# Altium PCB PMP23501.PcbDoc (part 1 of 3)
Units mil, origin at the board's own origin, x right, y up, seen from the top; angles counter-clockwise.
Board outline 4950 x 3450 mil, 4 copper layers (Top Layer, Layer 1, Layer 2, Bottom Layer), stack 70.356 mil thick; 186 components, 84 nets, 554 pads, 643 vias.
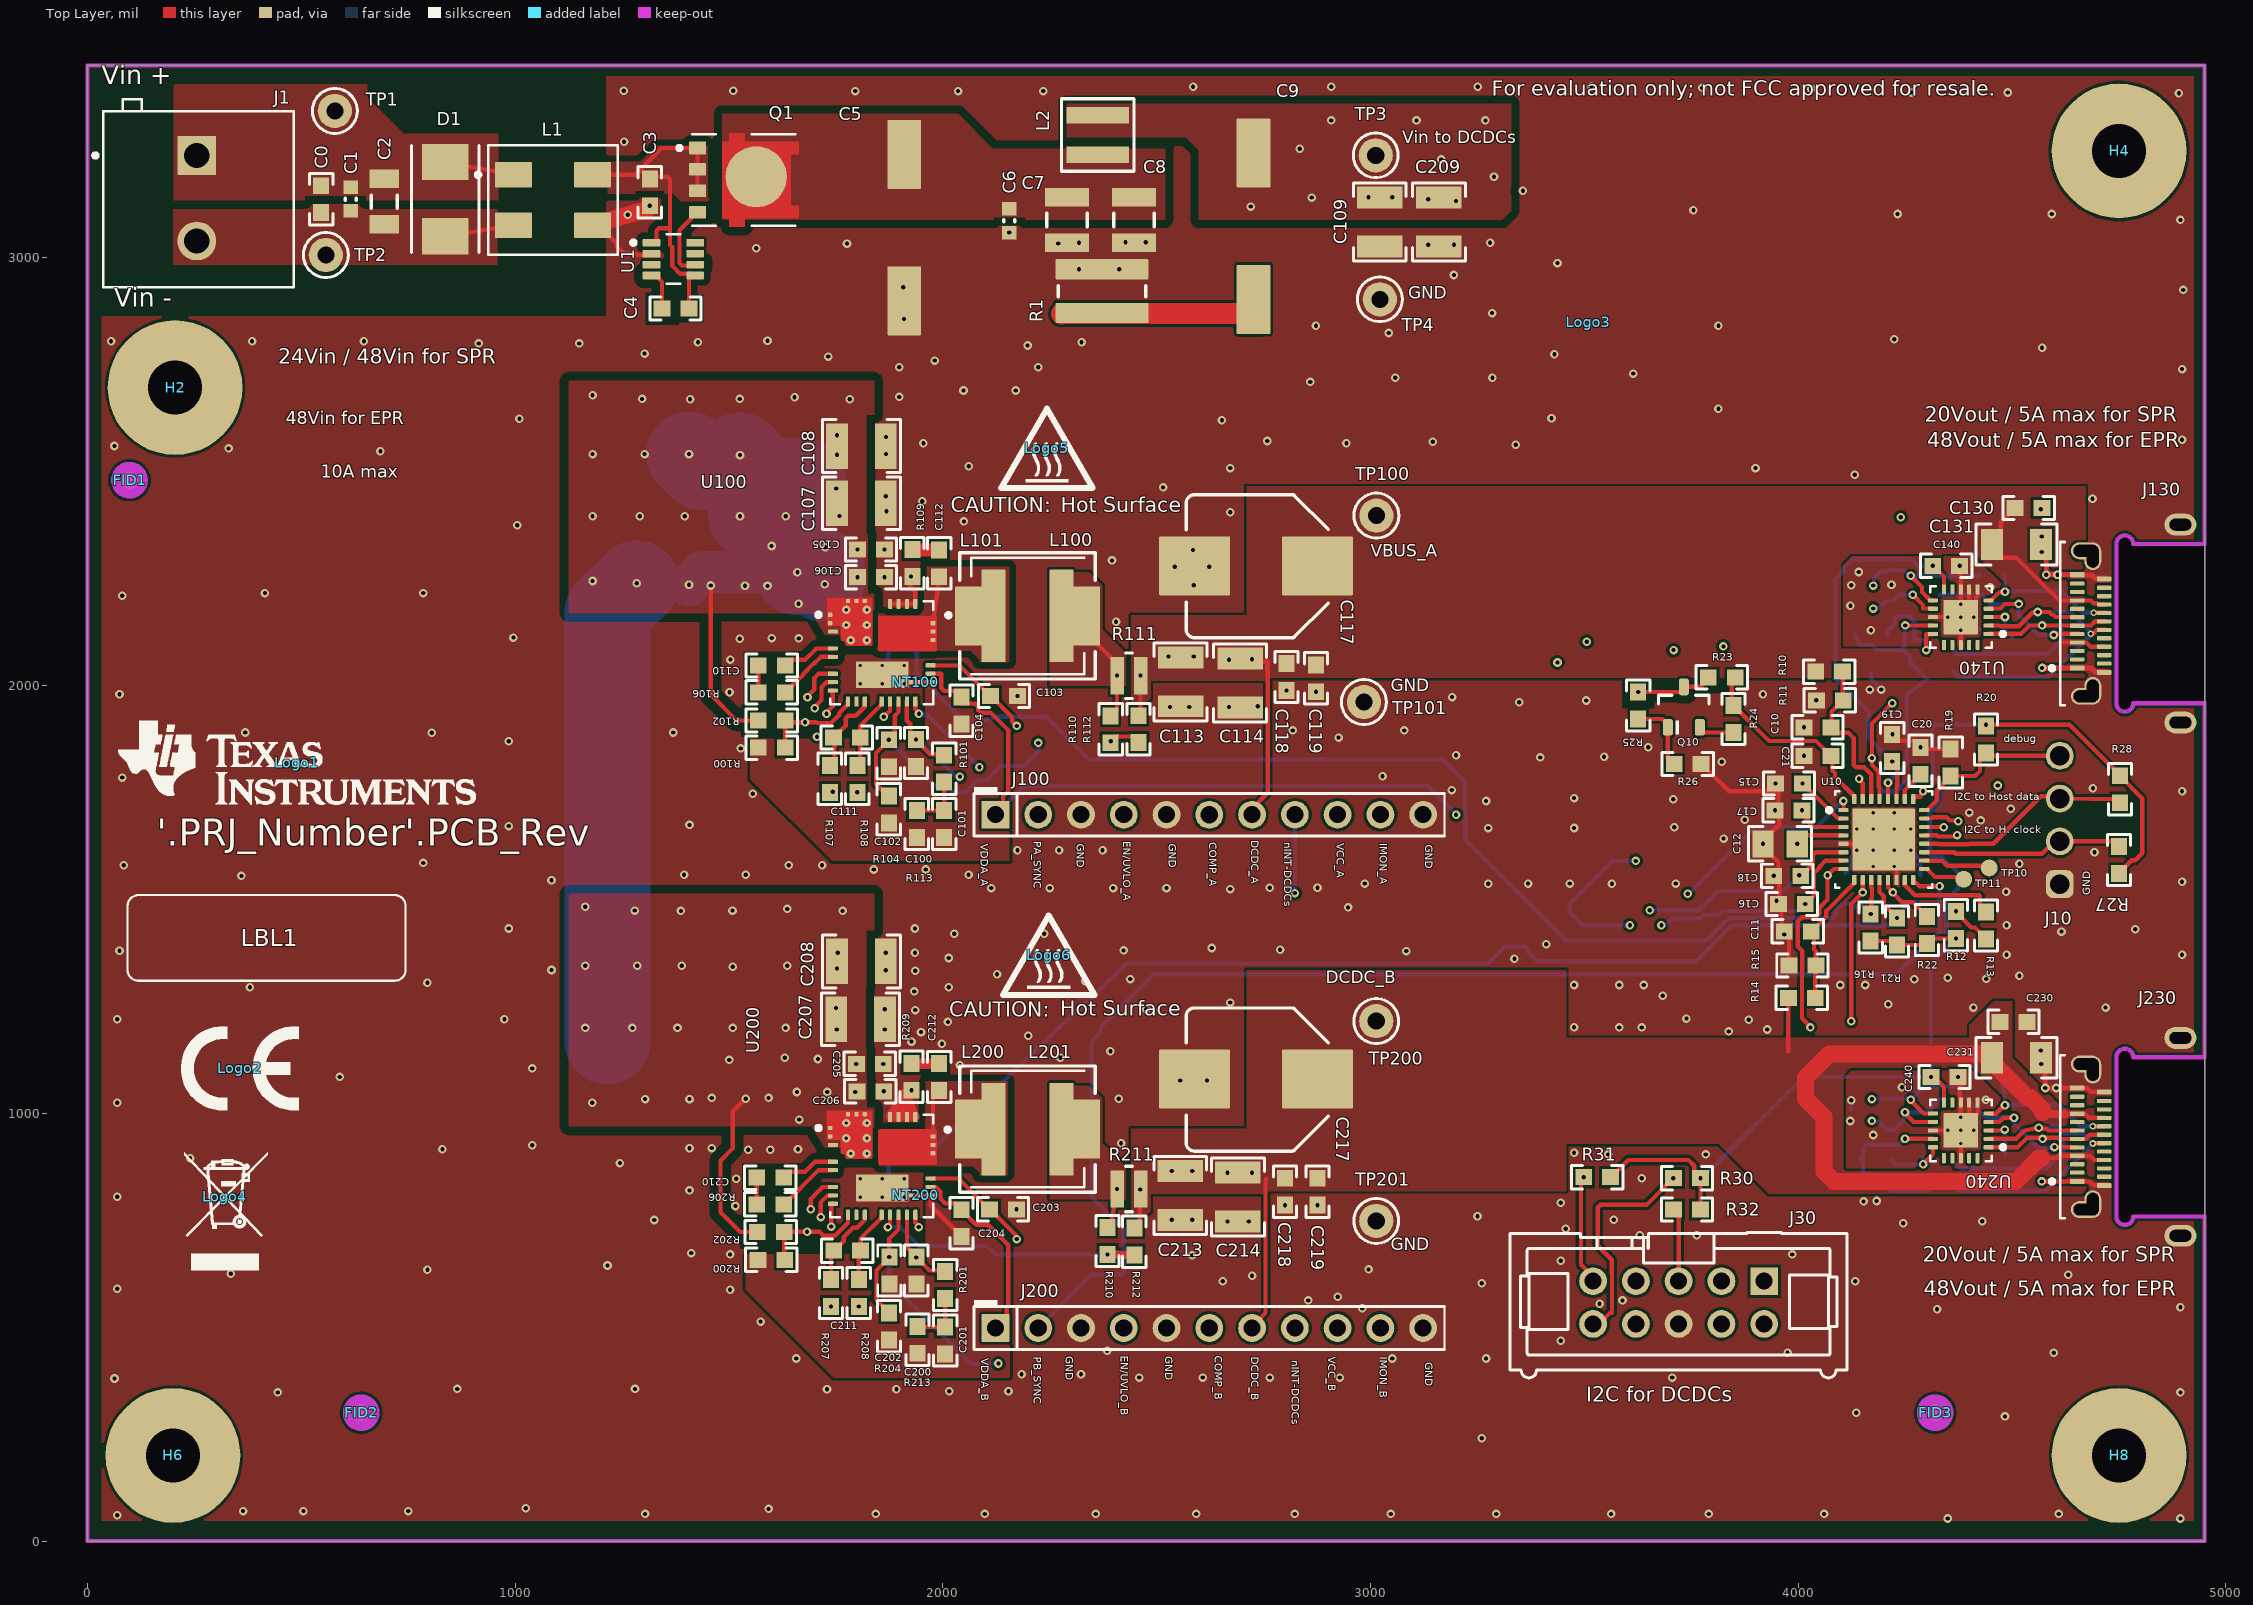
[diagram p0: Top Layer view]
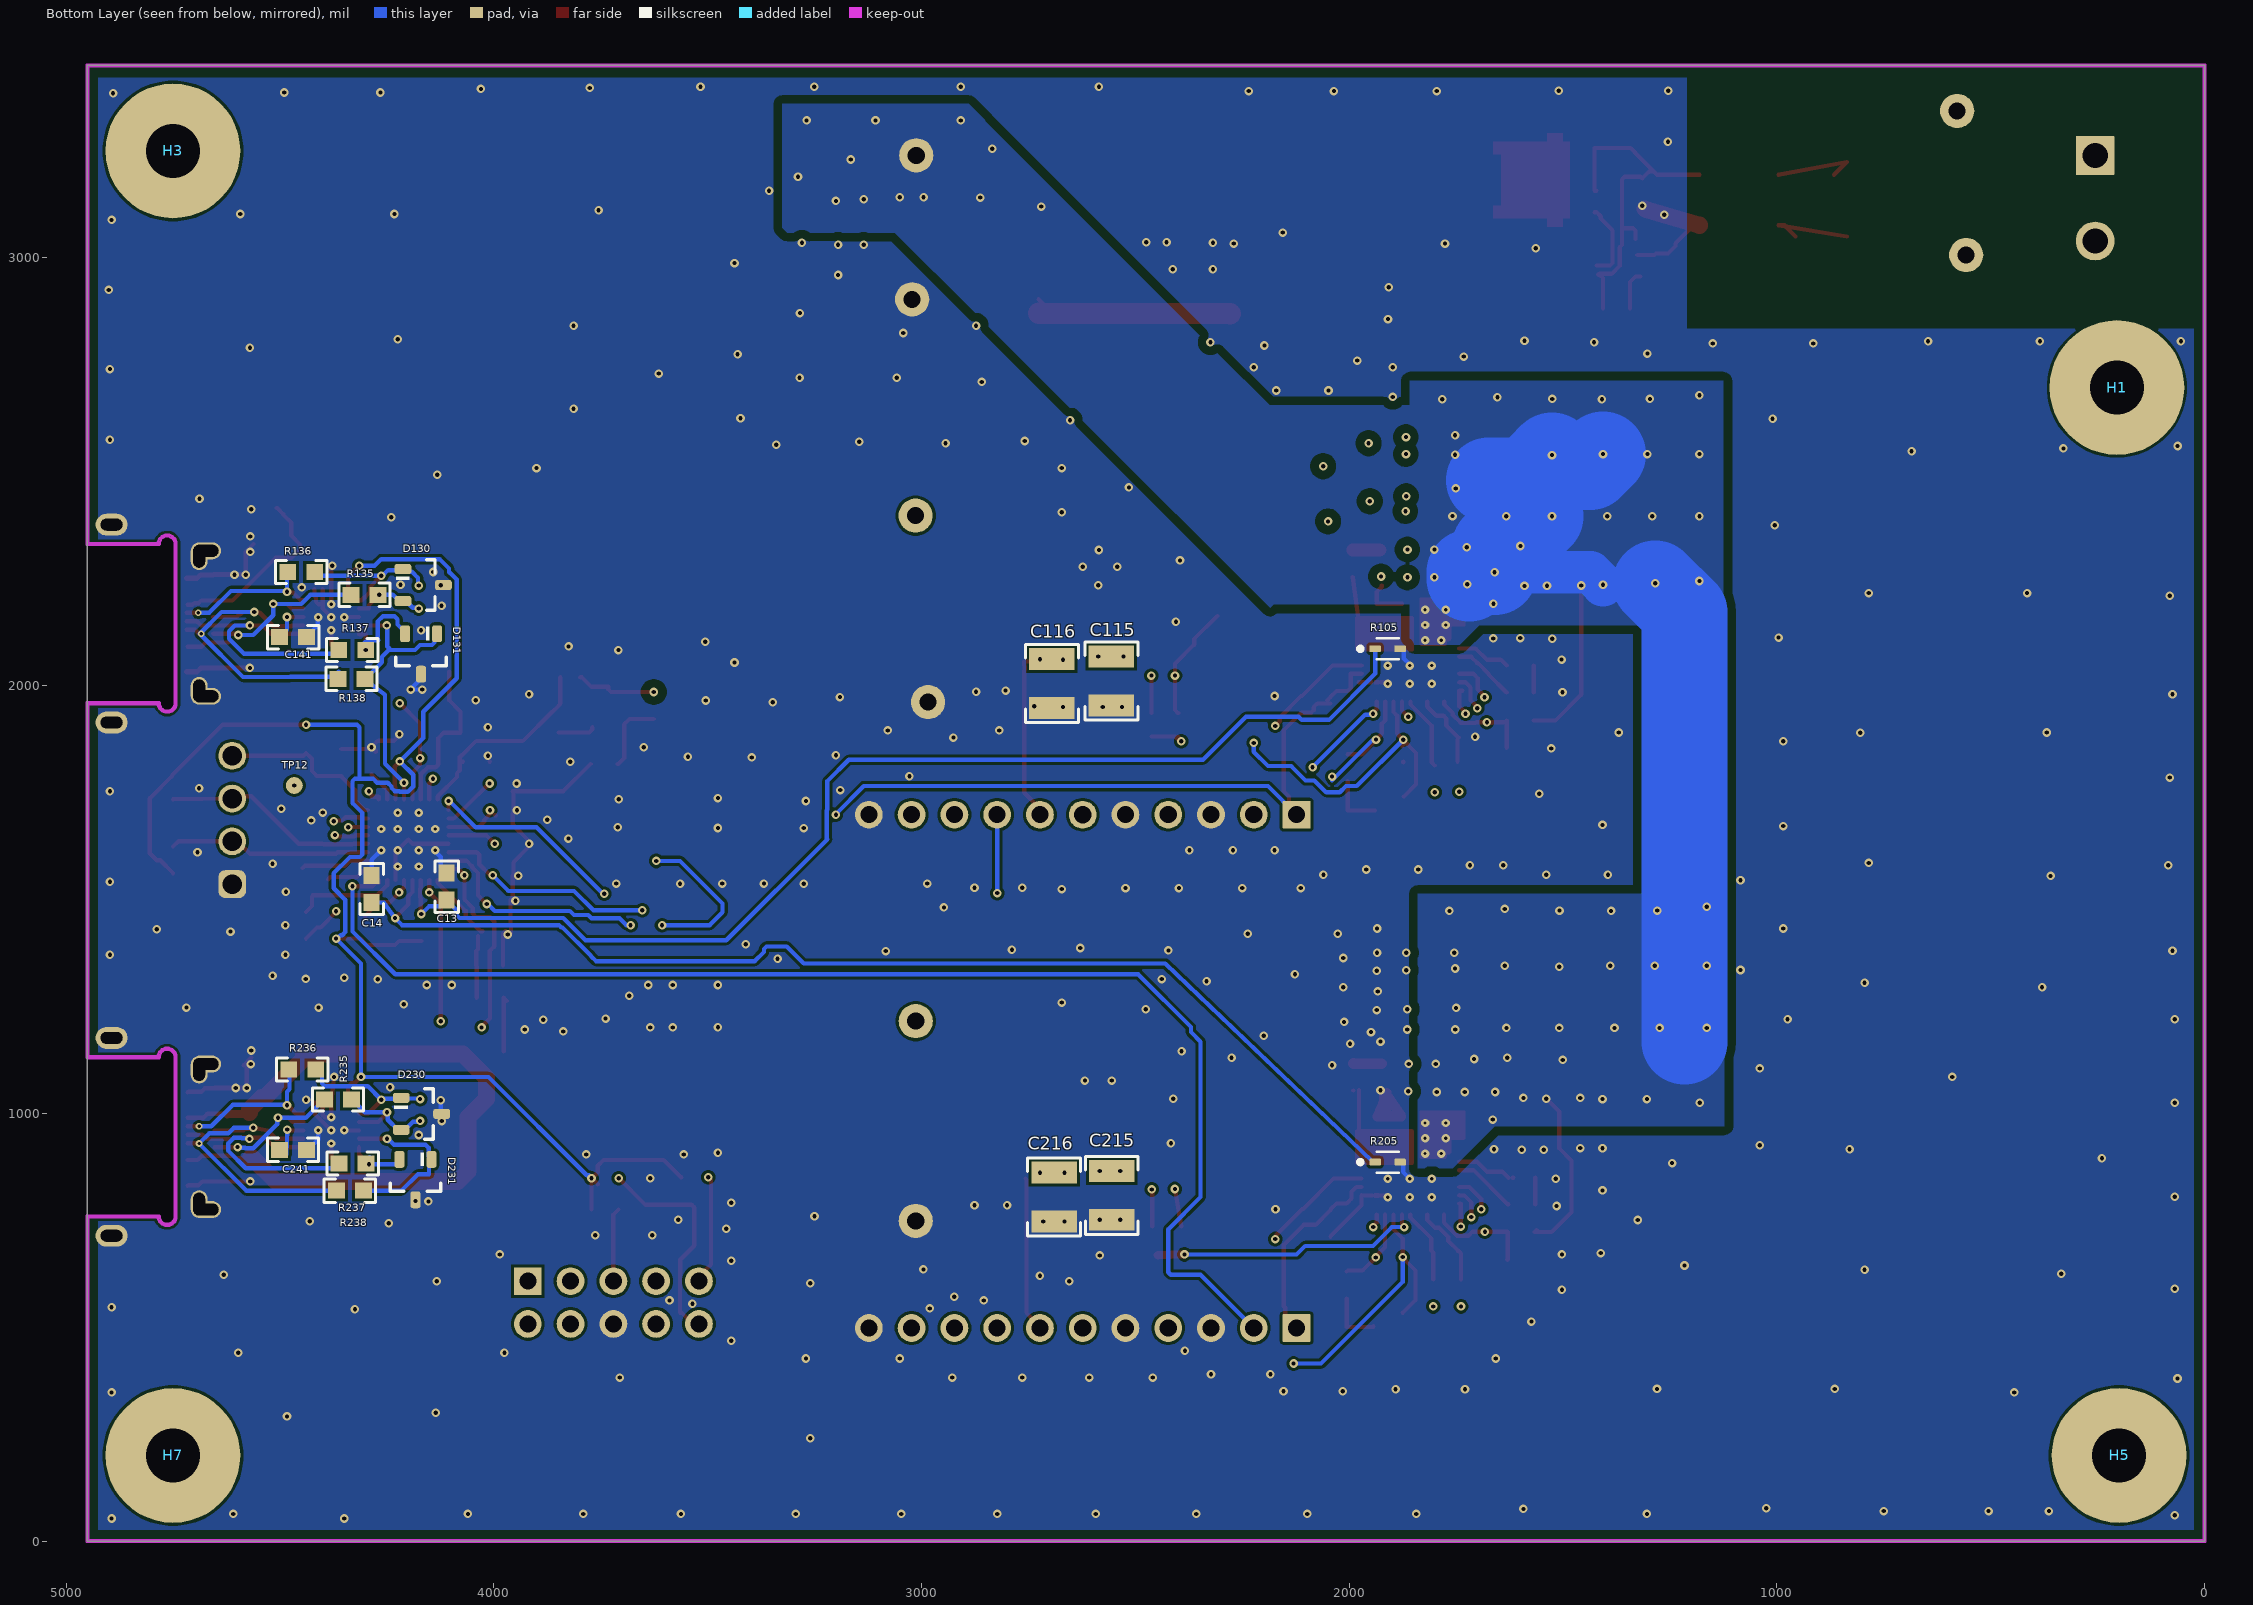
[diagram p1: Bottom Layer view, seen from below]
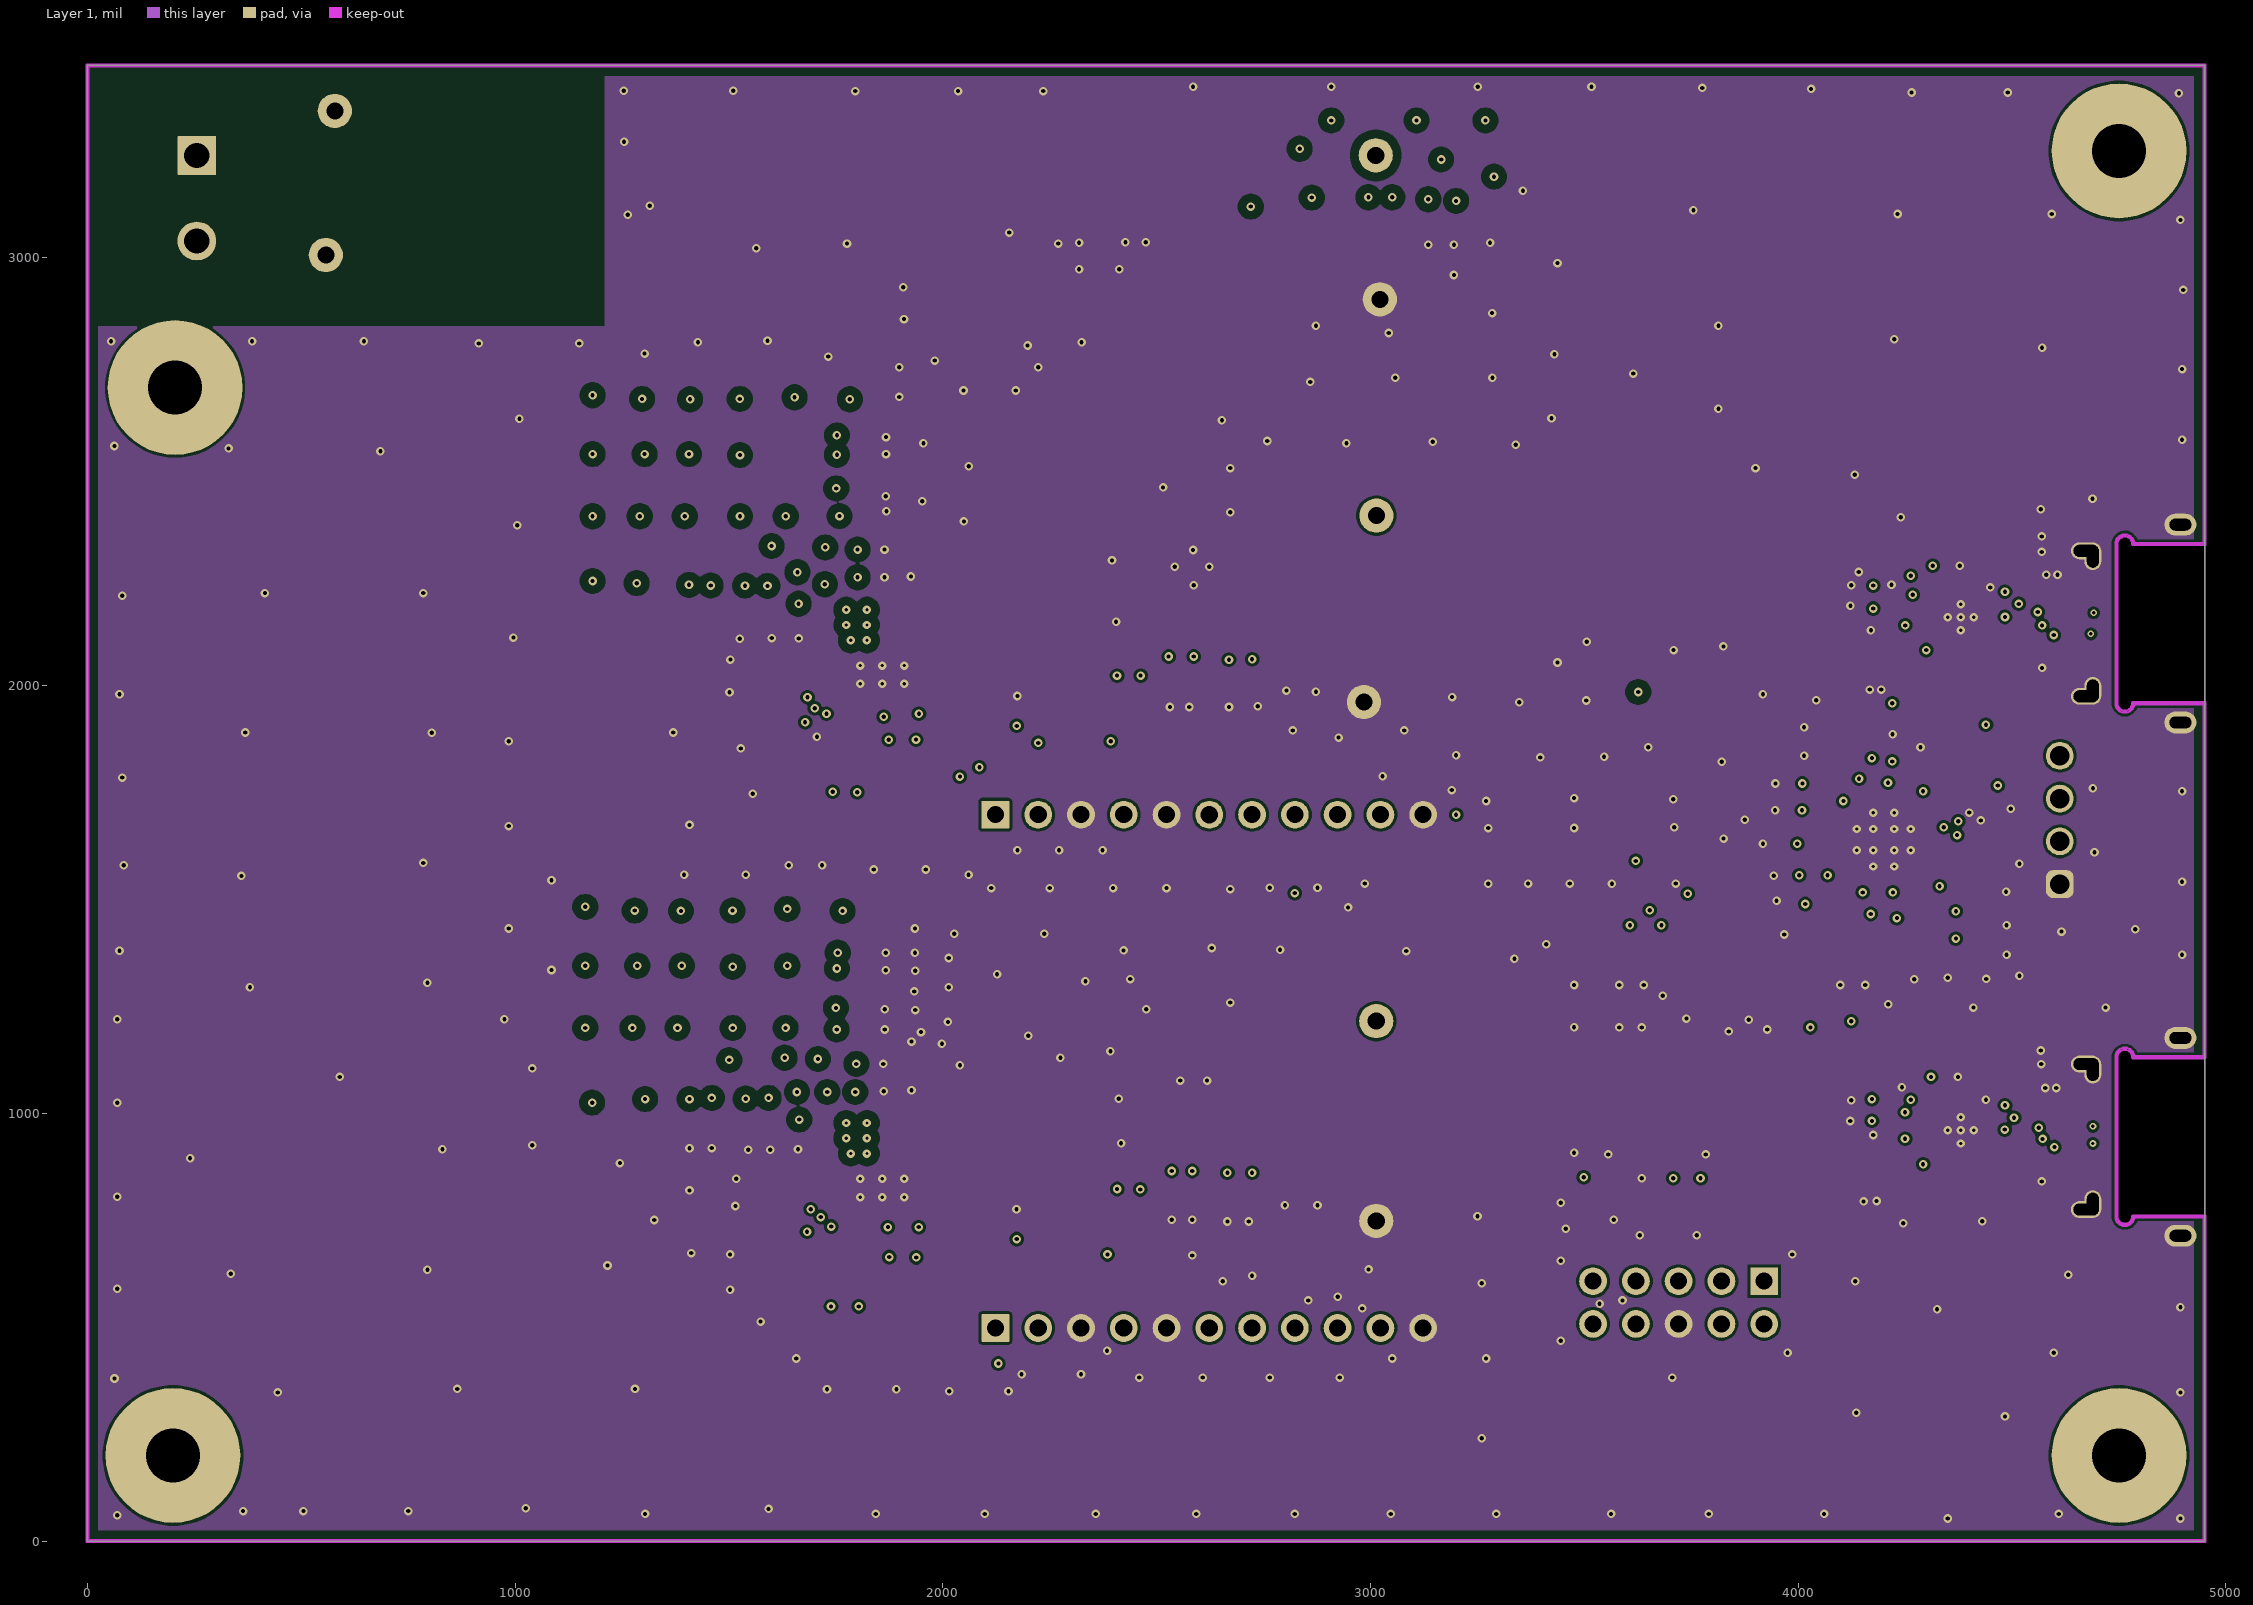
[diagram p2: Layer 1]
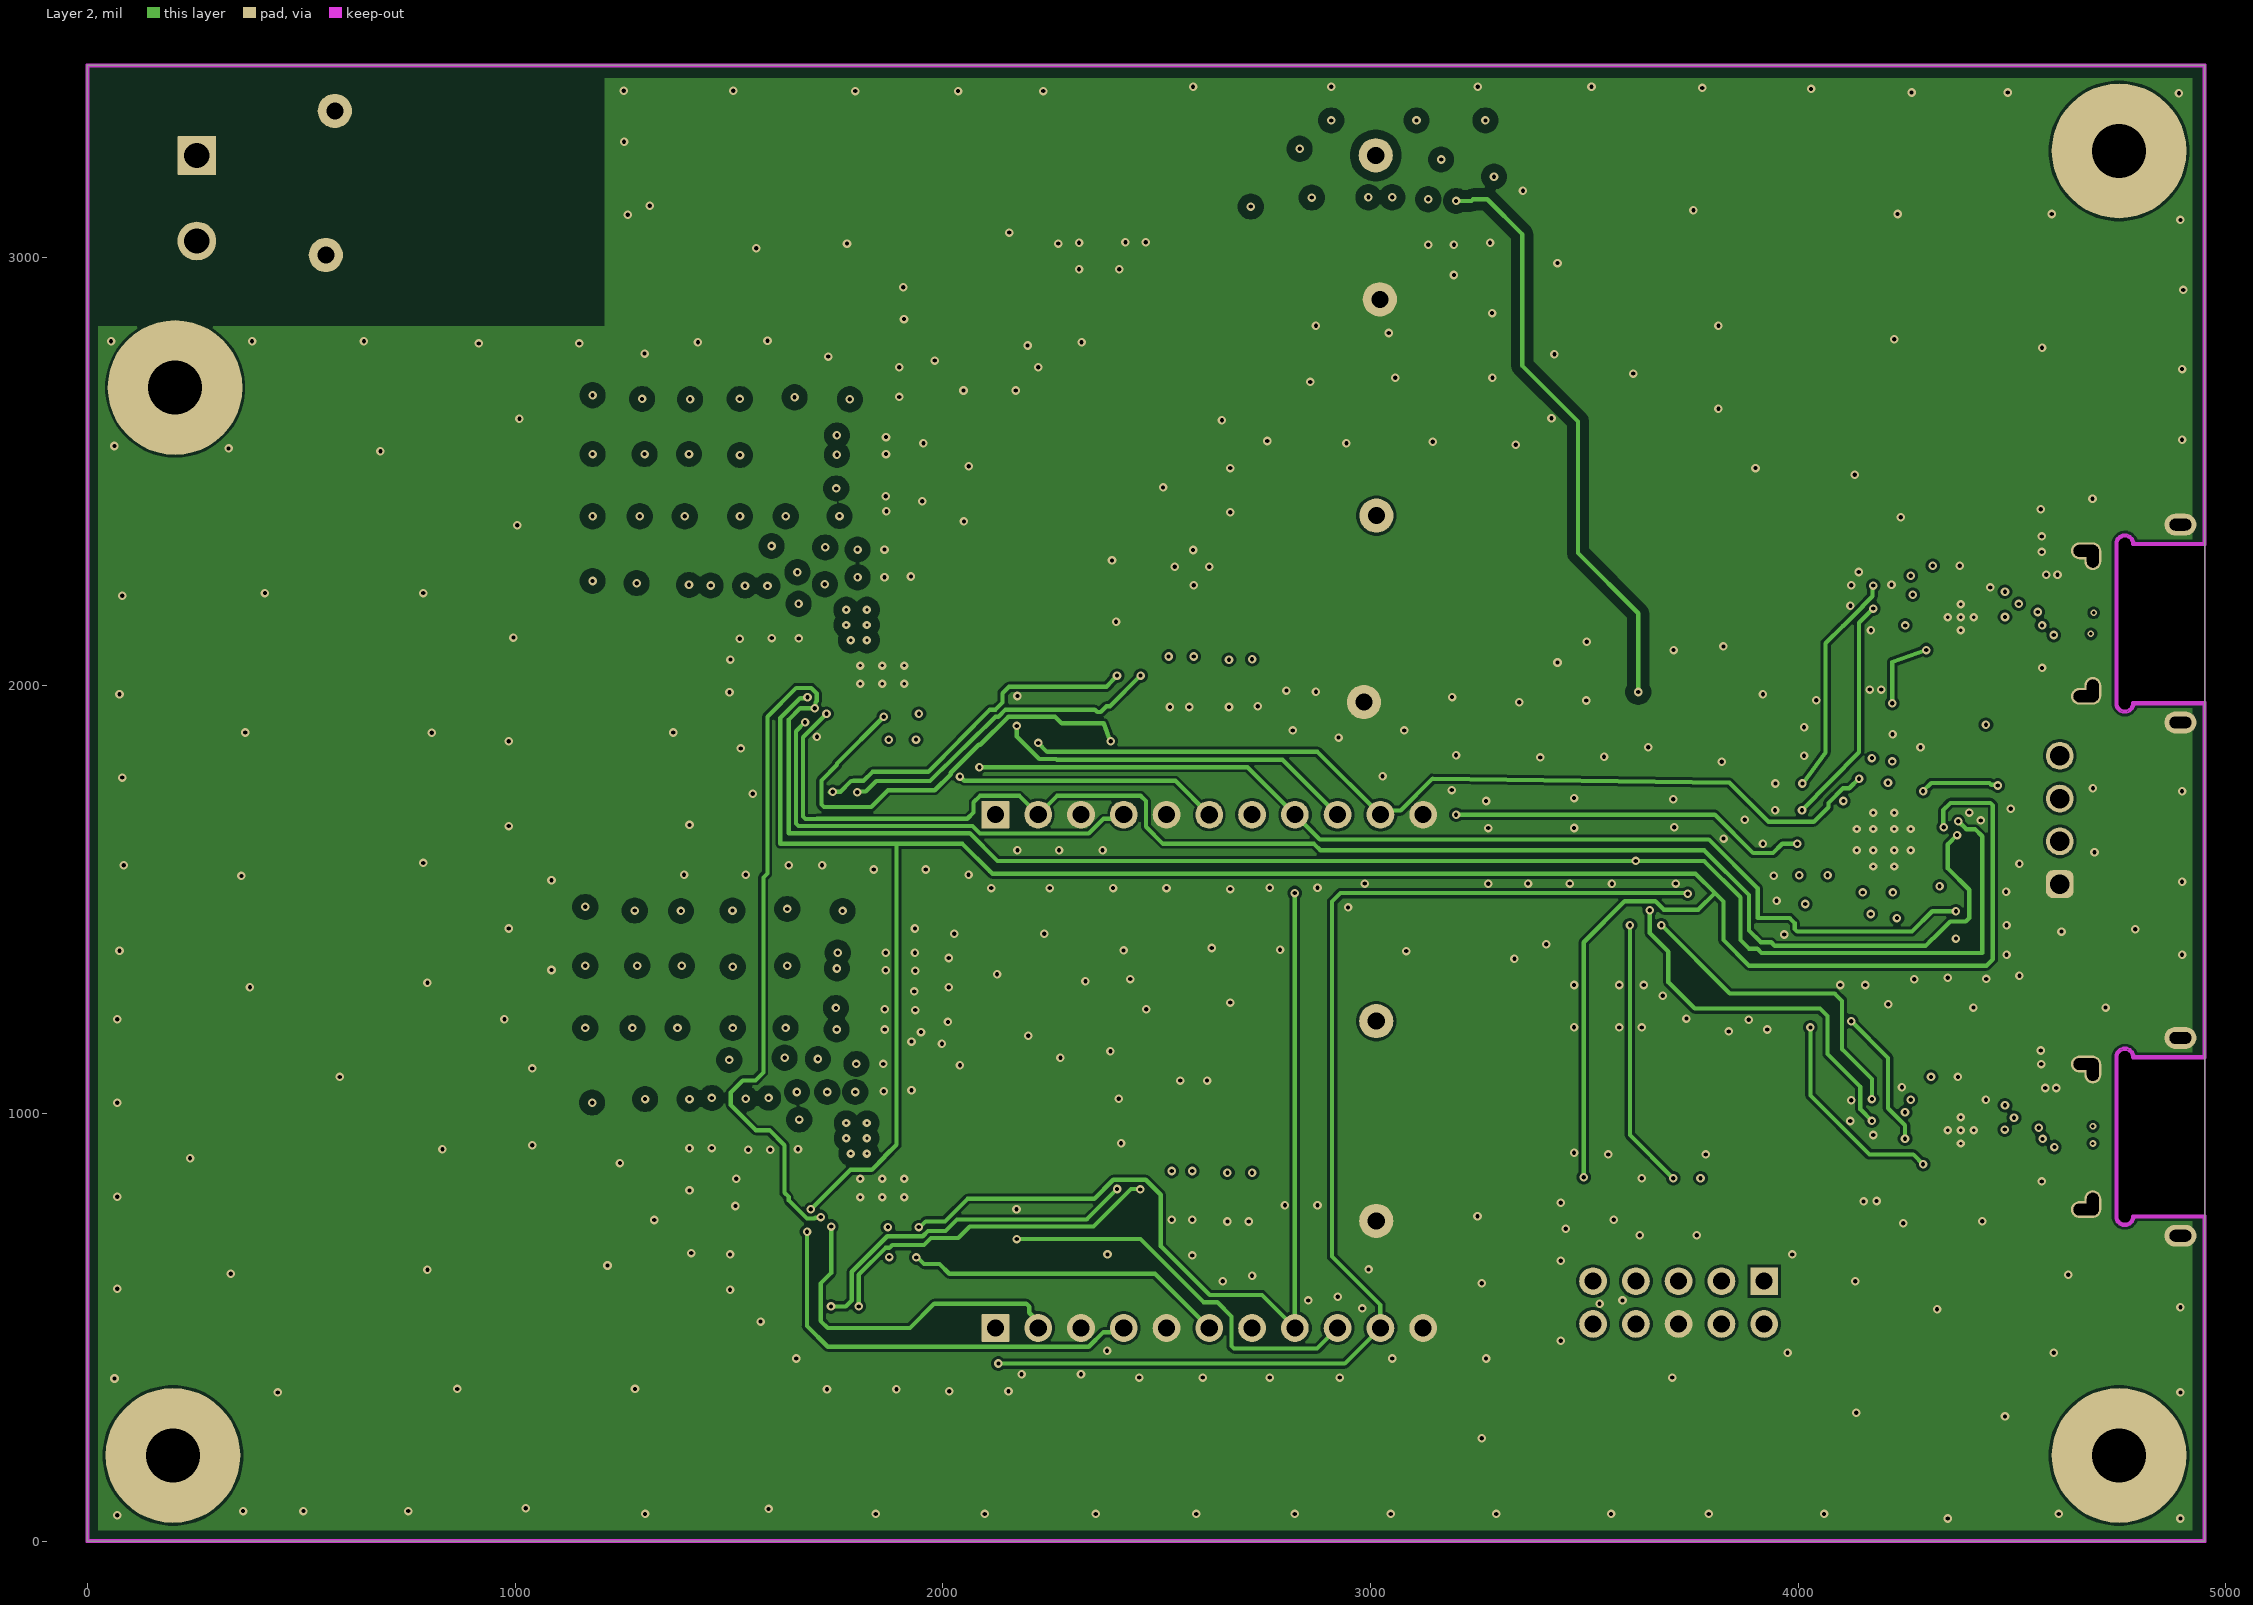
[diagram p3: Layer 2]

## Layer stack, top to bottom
Top Solder: solder mask 0.4, Solder Resist, Dk 3.5
Top Layer: signal copper 1.4
Dielectric 1: prepreg 2.8, PP-006, Dk 4.1
Layer 1: signal copper 1.378
Dielectric1: core 59.2, FR-4 High Tg, Dk 4.8
Layer 2: signal copper 1.378
Dielectric 2: prepreg 2.8, PP-006, Dk 4.1
Bottom Layer: signal copper 1.4
Bottom Solder: solder mask 0.4, Solder Resist, Dk 3.5

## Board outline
0,0 0,3450 4950,3450 4950,0

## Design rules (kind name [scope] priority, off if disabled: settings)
AcuteAngle [All] p1: minimum=4.50000000000000E+0001 checktracksonly=FALSE
AssemblyTestPointUsage [All] p1: valid=2
BoardOutlineClearance BoardOutlineClearance_MountingHoles [OnCopper and InComponentClass('Mounting Holes')] p1: gap=39.37 ignorepadtopadclearanceinfootprint=FALSE
BoardOutlineClearance BoardOutlineClearance_Poly [OnCopper and IsPoly] p2: gap=25 ignorepadtopadclearanceinfootprint=FALSE
BoardOutlineClearance [OnCopper and Not InComponentClass('Logo') and not InComponentClass('FiducialMark') and not InRegion(1000,500,4000,800) and not InPoly] p3: gap=19 ignorepadtopadclearanceinfootprint=FALSE
Clearance Clearance_1 [InNet('NetC3_1') vs InNet('GND')] p1: gap=15 ignorepadtopadclearanceinfootprint=TRUE
Clearance Clearance_4 [InNetClass('SW') vs InNetClass('LV')] p2: gap=15 ignorepadtopadclearanceinfootprint=TRUE
Clearance Clearance_3 [InNetClass('HV') vs InNetClass('SW')] p3: gap=14 ignorepadtopadclearanceinfootprint=TRUE
Clearance Clearance_2 [InNetClass('HV') vs InNetClass('LV')] p4: gap=20 ignorepadtopadclearanceinfootprint=TRUE
Clearance Clearance_FiducialMark [IsKeepOut and InComponentClass('FiducialMark') vs IsPad and InComponentClass('FiducialMark')] p5: gap=0 ignorepadtopadclearanceinfootprint=FALSE
Clearance [All] p6: gap=6.5 ignorepadtopadclearanceinfootprint=TRUE
Clearance Clearance_Keepouts [((IsTrack Or IsArc) And Not InPoly) And IsFree and IsKeepOut vs ((IsTrack Or IsArc) And Not InPoly) And IsFree and IsKeepOut] p7: gap=0 ignorepadtopadclearanceinfootprint=FALSE
Clearance Clearance_Poly [InPolygon] p8: gap=10 ignorepadtopadclearanceinfootprint=TRUE
ComponentClearance ComponentClearanceL1x [InComponent('L100') vs InComponent('L101')] p1: gap=0 collisioncheckmode=3 verticalgap=0 showdistances=FALSE
ComponentClearance ComponentClearanceU100 [InComponent('U100') vs InComponent('NT100')] p2: gap=0 collisioncheckmode=3 verticalgap=0 showdistances=FALSE
ComponentClearance ComponentClearanceU200 [InComponent('U200') vs InComponent('NT200')] p3: gap=0 collisioncheckmode=3 verticalgap=0 showdistances=FALSE
ComponentClearance ComponentClearanceL2x [InComponent('L200') vs InComponent('L201')] p4: gap=0 collisioncheckmode=3 verticalgap=0 showdistances=FALSE
ComponentClearance ComponentClearance_ScrewToNut [(HasFootprint('NY PMS 440 0025 PH')) vs (HasFootprint('Keystone_1902C'))] p5: gap=5 collisioncheckmode=3 verticalgap=10 showdistances=FALSE
ComponentClearance ComponentClearance_MountingHoles_FiducialMarks [InComponentClass('Mounting Holes') vs InComponentClass('FiducialMark')] p6: gap=50 collisioncheckmode=3 verticalgap=10 showdistances=FALSE
ComponentClearance ComponentClearance_MountingHoles [InComponentClass('Mounting Holes')] p7: gap=100 collisioncheckmode=3 verticalgap=100000 showdistances=FALSE
ComponentClearance ComponentClearance_1 [All] p8: gap=10 collisioncheckmode=3 verticalgap=10 showdistances=FALSE
ComponentClearance ComponentClearance_Shunt [InComponentClass('Header') vs InComponentClass('Shunt')] p9: gap=0 collisioncheckmode=3 verticalgap=0 showdistances=FALSE
ComponentClearance ComponentClearance_Logo [InComponentClass('Logo')] p10: gap=30 collisioncheckmode=3 verticalgap=10 showdistances=FALSE
ComponentClearance ComponentClearance_SmallPassives [HasFootprint('0201*') or HasFootprint('0402*') or HasFootprint('0508') or HasFootprint('0603*') or HasFootprint('0612') or HasFootprint('0805*') or HasFootprint('0815*') or HasFootprint('0830*') or HasFootprint('1206*') or HasFootprint('1210*') or HasFootprint('1808*') or HasFootprint('1812*') or HasFootprint('1825*') or HasFootprint('2010*') or HasFootprint('2220*') or HasFootprint('2225*') or HasFootprint('2512*') or HasFootprint('2728*') or HasFootprint('3518*') vs HasFootprint('0201*') or HasFootprint('0402*') or HasFootprint('0508') or HasFootprint('0603*') or HasFootprint('0612') or HasFootprint('0805*') or HasFootprint('0815*') or HasFootprint('0830*') or HasFootprint('1206*') or HasFootprint('1210*') or HasFootprint('1808*') or HasFootprint('1812*') or HasFootprint('1825*') or HasFootprint('2010*') or HasFootprint('2220*') or HasFootprint('2225*') or HasFootprint('2512*') or HasFootprint('2728*') or HasFootprint('3518*')] p11: gap=14.96 collisioncheckmode=3 verticalgap=10 showdistances=FALSE
ComponentClearance ComponentClearance_THtoSMT [IsThruComponent vs IsSMTComponent] p12: gap=30 collisioncheckmode=3 verticalgap=30 showdistances=FALSE
ComponentClearance ComponentClearance_THtoTH [IsThruComponent vs IsThruComponent] p13: gap=20 collisioncheckmode=3 verticalgap=30 showdistances=FALSE
DiffPairsRouting [All] p1: maxlimit=100 minlimit=10 mostfreqgap=10 toplayer_minwidth=15 toplayer_maxwidth=15 toplayer_prefwidth=15 midlayer1_minwidth=15 midlayer1_maxwidth=15 midlayer1_prefwidth=15 midlayer2_minwidth=15 midlayer2_maxwidth=15 midlayer2_prefwidth=15 bottomlayer_minwidth=15 bottomlayer_maxwidth=15 bottomlayer_prefwidth=15 maxuncoupledlength=1000
FabricationTestPointUsage TestPointUsage [All] p1: valid=2 allowmultiple=FALSE
FabricationTestpoint Testpoint [All] p1: side=3 testpointundercomponent=TRUE minsize=40 maxsize=100 preferedsize=60 minholesize=0 maxholesize=40 preferedholesize=32 testpointgrid=1 allowsidetop=TRUE allowsidebottom=TRUE usegrid=TRUE gridtolerance=0.01
FanoutControl Fanout_LCC [IsLCC] p1: bgadir=Out bgaviamode=Centered fanoutstyle=Auto fanoutdirection=Alternating viagrid=1 // Fanout_LCC (Default Rule)
FanoutControl Fanout_BGA [IsBGA] p2: bgadir=Out bgaviamode=Centered fanoutstyle=Auto fanoutdirection=Alternating viagrid=1 // Fanout_BGA (Default Rule)
FanoutControl Fanout_Default [All] p4: bgadir=Out bgaviamode=Centered fanoutstyle=Auto fanoutdirection=Alternating viagrid=1 // Fanout_Default (Default Rule)
FanoutControl Fanout_Small [(CompPinCount < 5)] p5: bgadir=Out bgaviamode=Centered fanoutstyle=Auto fanoutdirection=OutThenIn viagrid=1 // Fanout_Small (Default Rule)
HoleSize [All] p1: absolutevalues=TRUE maxlimit=251 minlimit=7.87 maxpercent=80.000 minpercent=20.000
MinimumAnnularRing MinimumAnnularRing_ThermalPadVias [IsVia and InAnyComponent] p1: minimumring=5
MinimumAnnularRing [All] p2: minimumring=5
MinimumSolderMaskSliver MinimumSolderMaskSliver_Logo [InComponentClass('Logo') vs InComponentClass('Logo')] p1: minsoldermaskwidth=0.7
MinimumSolderMaskSliver [All] p2: minsoldermaskwidth=3.94
PlaneConnect [All] p1: planeconnectstyle=Relief reliefexpansion=10 reliefentries=4 reliefconductorwidth=10 reliefairgap=10
PolygonConnect PolygonConnect_9 [All vs IsNamedPolygon('LAYER_1_GND_P005')] p1: connectstyle=Direct reliefconductorwidth=10 reliefentries=4 polygonreliefangle="90 Angle" airgapwidth=10
PolygonConnect PolygonConnect_8 [All vs IsNamedPolygon('TOP_LAYER_DCDC_A_P004')] p2: connectstyle=Direct reliefconductorwidth=10 reliefentries=4 polygonreliefangle="90 Angle" airgapwidth=10
PolygonConnect PolygonConnect_7 [All vs IsNamedPolygon('TOP_LAYER_NETC112_1_P003')] p3: connectstyle=Direct reliefconductorwidth=10 reliefentries=4 polygonreliefangle="90 Angle" airgapwidth=10
PolygonConnect PolygonConnect_6 [All vs IsNamedPolygon('TOP_LAYER_NETL100_2_P003')] p4: connectstyle=Direct reliefconductorwidth=10 reliefentries=4 polygonreliefangle="90 Angle" airgapwidth=10
PolygonConnect PolygonConnect_5 [All vs IsNamedPolygon('TOP_LAYER_VIN_48_P000')] p5: connectstyle=Direct reliefconductorwidth=10 reliefentries=4 polygonreliefangle="90 Angle" airgapwidth=10
PolygonConnect PolygonConnect_4 [All vs IsNamedPolygon('LAYER_1_GND_P005')] p6: connectstyle=Direct reliefconductorwidth=10 reliefentries=4 polygonreliefangle="90 Angle" airgapwidth=10
PolygonConnect PolygonConnect_3 [All] p7: connectstyle=Direct reliefconductorwidth=10 reliefentries=4 polygonreliefangle="90 Angle" airgapwidth=10
PolygonConnect PolygonConnect_2 [All vs IsNamedPolygon('TOP_LAYER_DCDC_A_P004')] p8: connectstyle=Direct reliefconductorwidth=10 reliefentries=4 polygonreliefangle="90 Angle" airgapwidth=10
PolygonConnect PolygonConnect_1 [All] p9: connectstyle=Direct reliefconductorwidth=10 reliefentries=4 polygonreliefangle="90 Angle" airgapwidth=10
PolygonConnect [All] p10: connectstyle=Direct reliefconductorwidth=10 reliefentries=4 polygonreliefangle="90 Angle" airgapwidth=10
RoutingVias ThermalPadVias [IsVia and InAnyComponent] p1: holewidth=7.87 width=19.68 viastyle="Through Hole" minholewidth=7.87 minwidth=19.68 maxholewidth=12.99 maxwidth=23.62
RoutingVias [All] p2: holewidth=10 width=20 viastyle="Through Hole" minholewidth=7.87 minwidth=16 maxholewidth=40 maxwidth=65
SilkToBoardRegionClearance [Not ((IsComment or IsDesignator) And (Hide <> 'False')) and not InRegion(1000,500,4000,800)] p1:
SilkToSilkClearance SilkToSilkClearance_Pb-FreeLogo [(HasFootprint('Pb-Free_Overlay_Medium') OR HasFootprint('Pb-Free_Overlay_Small')) vs (HasFootprint('Pb-Free_Overlay_Medium') OR HasFootprint('Pb-Free_Overlay_Small'))] p1: silktosilkclearance=0
SilkToSilkClearance [All] p2: silktosilkclearance=3.94
SilkToSolderMaskClearance SilkToComponentPadClearance [(IsPad or IsFill or IsRegion) and InAnycomponent] p1: minsilkscreentomaskgap=5 clearancetoexposedcopper=TRUE
SilkToSolderMaskClearance "Silk to Solder Mask Opening" [All] p2: minsilkscreentomaskgap=3.94 clearancetoexposedcopper=FALSE
SolderMaskExpansion [All] p1: expansion=1.97 istentingtop=FALSE
UnRoutedNet [All] p1: checkbadconnections=TRUE
Width [All] p1: maxlimit=200 minlimit=6 preferedwidth=10 minimp=50.000000 maximp=50.000000 favimp=50.000000 checkconnectedcopper=TRUE
14 further rules are at their usual default settings.

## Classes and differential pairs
net class SW: NetC110_1 NetC110_2 NetC112_1 NetC210_1 NetC210_2 NetC212_1 NetR106_2 NetR206_2
net class LV: AGND_A AGND_B EMIGND EN/UVLO_A EN/UVLO_B GND I2CtoDCDC-clk I2CtoDCDC-data NetC9_2 NetC112_2 NetC212_2 PA_SYNC PB_SYNC
net class HV: NetC0_1 NetC3_1 NetC4_2 NetQ1_4 V_Batt_Protected Vin_48
component class USB-Cconecctors&protection: C130 C131 C140 C141 C230 C231 C240 C241 D130 D131 D230 D231 J130 J230 R135 R136 R137 R138 R235 R236 R237 R238 U140 U240
component class InputPower&Protection: C0 C1 C2 C3 C4 C5 C6 C7 C8 C9 D1 J1 L1 L2 Q1 R1 TP1 TP2 TP3 TP4 U1
component class Header: J10 J100 J200
component class EPR_Controller_Dual: C10 C11 C12 C13 C14 C15 C16 C17 C18 C19 C20 C21 J10 Q10 R10 R11 R12 R13 R14 R15 R16 R19 R20 R21 R22 R23 R24 R25 R26 R27 R28 TP10 TP11 TP12 U10
component class DCDC_B: C200 C201 C202 C203 C204 C205 C206 C207 C208 C209 C210 C211 C212 C213 C214 C215 C216 C217 C218 C219 J200 L200 L201 NT200 R200 R201 R202 R204 R205 R206 R207 R208 R209 R210 R211 R212 R213 TP200 TP201 U200
component class DCDC_A: C100 C101 C102 C103 C104 C105 C106 C107 C108 C109 C110 C111 C112 C113 C114 C115 C116 C117 C118 C119 J30 J100 L100 L101 NT100 R30 R31 R32 R100 R101 R102 R104 R105 R106 R107 R108 R109 R110 R111 R112 R113 TP100 TP101 U100
component class "Mounting Holes": H2 H4 H6 H8
component class Logo: Logo1
component class PMP23501_Hardware: FID1 FID2 FID3 H1 H2 H3 H4 H5 H6 H7 H8 LBL1 Logo1 Logo2 Logo3 Logo4 Logo5 Logo6 ZZ1 ZZ2 ZZ3 ZZ4
component class FiducialMark: FID1 FID2 FID3
component class AssemblyNote: ZZ1 ZZ2 ZZ3 ZZ4
component class Label: LBL1

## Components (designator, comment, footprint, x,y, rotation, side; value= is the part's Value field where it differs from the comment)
C0 "CGA3E2X7R2A102K080AA" 0603 546.49,3137.23 r270 top value=1000pF
C1 "GCJ188R72A104KA01D" 0603L 615.39,3137.23 r270 top value=0.1uF
C2 "CGA5L3X7S2A225K160AB" 1206_180L 694.13,3131.33 r270 top value=2.2uF
C3 "CGA3E2X7R2A102K080AA" 0603 1315.02,3153.23 r270 top value=1000pF
C4 "GCM188R71H104KA57D" 0603 1375,2881.48 r180 top value=0.1uF
C5 "EEE-TG2A330P" TG_V_1000x1020 1909.45,3070.87 r270 top value=33uF
C6 "GCJ188R72A104KA01D" 0603L 2155.51,3086.77 r270 top value=0.1uF
C7 "GCM32DC72A475KE02L" 1210_220L 2290.07,3088.58 r270 top value=4.7uF
C8 "GCM32DC72A475KE02L" 1210_220L 2446.85,3088.58 r270 top value=4.7uF
C9 "EEE-TG2A330P" TG_V_1000x1020 2726.38,3074.35 r270 top value=33uF
C10 "GCJ188R72A104KA01D" 0603 4044.98,1902.49 r180 top value=0.1uF
C11 "GCJ188R72A104KA01D" 0603 3998.73,1425.48 r180 top value=0.1uF
C12 "GCJ21BR71A106KE01L" 0805_HV 3957.48,1630.16 r180 top value=10uF
C13 "CGA3E2X7R2A103K080AA" 0603 4110,1530 r90 bottom value=0.01uF
C14 "CGA3E2X7R2A103K080AA" 0603 4285.51,1524.5 r90 bottom value=0.01uF
C15 "GRM188R72A221KA01D" 0603 3978.19,1771.1 r0 top value=220pF
C16 "GRM188R72A221KA01D" 0603 3985,1489.31 r180 top value=220pF
C17 "GRM188R72A221KA01D" 0603 3977.25,1708.5 r0 top value=220pF
C18 "GRM188R72A221KA01D" 0603 3974.31,1555.1 r180 top value=220pF
C19 "GRM188Z71A475ME15D" 0603 4219.65,1854.25 r270 top value=4.7uF
C20 "GCM188R71E474KA64D" 0603 4285.8,1824.06 r90 top value=0.47uF
C21 "CGA3E1X7R1V105K080AE" 0603 4044.98,1835.85 r0 top value=1uF
C100 "GCM1885C2A100JA16D" 0603 1937.29,1842.24 r270 top value=10pF
C101 "GCM188R72A332KA37D" 0603 2003.27,1676.58 r270 top value=3300pF
C102 "GCM1885C2A100JA16D" 0603 1873.73,1841.93 r270 top value=10pF
C103 "GRM188Z71A475ME15D" 0603 2143,1975.74 r0 top value=4.7uF
C104 "GRM188C80J226ME15D" 0603 2043.5,1941.46 r90 top value=22uF
C105 "CGA3E3X7S2A473K080AB" 0603 1832.09,2318.1 r0 top value=0.047uF
C106 "CGA3E2X7R2A102K080AA" 0603 1832.09,2253.32 r0 top value=1000pF
C107 "GCM32DC72A475KE02L" 1210_220 1809.53,2426.13 r0 top value=4.7uF
C108 "GCM32DC72A475KE02L" 1210_220 1809.53,2560 r0 top value=4.7uF
C109 "GCM32DC72A475KE02L" 1210_220 3021.65,3083.97 r270 top value=4.7uF
C110 "CGA3E2X7R1H473K080AA" 0603 1600.07,2046.84 r0 top value=0.047uF
C111 "CGA3E2NP01H330J080AA" 0603 1775.53,1878.56 r0 top value=33pF
C112 "placeholder" 0603 1991.54,2285.88 r90 top value=100pF
C113 "CGA6M3X7S2A475K200AB" 1210_220 2555.98,2008.7 r270 top value=4.7uF
C114 "CGA6M3X7S2A475K200AB" 1210_220 2695.08,2006.3 r270 top value=4.7uF
C115 "CGA6M3X7S2A475K200AB" 1210_220 2555.98,2010.91 r270 bottom value=4.7uF
C116 "CGA6M3X7S2A475K200AB" 1210_220 2695.08,2004.86 r270 bottom value=4.7uF
C117 "8mm diameter placeholder for layout" HXB_HA0 2750,2280 r180 top locked value=47uF
C118 "CGA3E3X7S2A473K080AB" 0603 2803.35,2019.93 r270 top value=0.047uF
C119 "CGA3E2X7R2A102K080AA" 0603 2872.25,2016.98 r270 top value=1000pF
C130 "GCM188R71H104KA57D" 0603 4538.61,2415.03 r0 top value=0.1uF
C131 "GCM31MR71H105KA55L" 1206 4510,2330 r0 top value=1uF
C140 "GCJ188R72A104KA01D" 0603 4345.78,2280.06 r0 top value=0.1uF
C141 "GCJ188R72A104KA01D" 0603 4469.1,2113.31 r180 bottom value=0.1uF
C200 "GCM1885C2A100JA16D" 0603 1938.02,632.42 r270 top value=10pF
C201 "GCM188R72A332KA37D" 0603 2005.37,468.92 r270 top value=3300pF
C202 "GCM1885C2A100JA16D" 0603 1875.03,632.42 r270 top value=10pF
C203 "GRM188Z71A475ME15D" 0603 2140.77,775.56 r0 top value=4.7uF
C204 "GRM188C80J226ME15D" 0603 2043.5,743.08 r90 top value=22uF
C205 "CGA3E3X7S2A473K080AB" 0603 1829.36,1115.52 r0 top value=0.047uF
C206 "CGA3E2X7R2A102K080AA" 0603 1830.42,1051.28 r0 top value=1000pF
C207 "GCM32DC72A475KE02L" 1210_220 1807.79,1220 r0 top value=4.7uF
C208 "GCM32DC72A475KE02L" 1210_220 1809.53,1355 r0 top value=4.7uF
C209 "GCM32DC72A475KE02L" 1210_220 3160,3083.97 r270 top value=4.7uF
C210 "CGA3E2X7R1H473K080AA" 0603 1596.61,849.54 r0 top value=0.047uF
C211 "CGA3E2NP01H330J080AA" 0603 1776.35,678.92 r0 top value=33pF
C212 "placeholder" 0603 1991.5,1085.03 r90 top value=100pF
C213 "CGA6M3X7S2A475K200AB" 1210_220 2555,808 r270 top value=4.7uF
C214 "CGA6M3X7S2A475K200AB" 1210_220 2690,804.17 r270 top value=4.7uF
C215 "CGA6M3X7S2A475K200AB" 1210_220 2555,808.1 r270 bottom value=4.7uF
C216 "CGA6M3X7S2A475K200AB" 1210_220 2690,804.17 r270 bottom value=4.7uF
C217 "8mm diameter placeholder for layout" HXB_HA0 2750,1080 r180 top locked value=47uF
C218 "CGA3E3X7S2A473K080AB" 0603 2799.83,816.73 r270 top value=0.047uF
C219 "CGA3E2X7R2A102K080AA" 0603 2875.98,816.73 r270 top value=1000pF
C230 "GCM188R71H104KA57D" 0603 4503.11,1213.84 r0 top value=0.1uF
C231 "GCM31MR71H105KA55L" 1206 4510,1130 r0 top value=1uF
C240 "GCJ188R72A104KA01D" 0603 4341.81,1085 r0 top value=0.1uF
C241 "GCJ188R72A104KA01D" 0603 4469.24,914.75 r180 bottom value=0.1uF
D1 "SMBJ70CA-13-F" SMB-Bi 836.61,3137.23 r90 top value=70V
D130 "SM24T1G" SOT-23 4165,2235 r180 bottom value=5V
D131 "SM24T1G" SOT-23 4170,2074 r270 bottom value=5V
D230 "SM24T1G" SOT-23 4169.01,998.7 r180 bottom value=5V
D231 "SM24T1G" SOT-23 4183.09,844.95 r270 bottom value=5V
FID1 "Fiducial" Fiducial10-20 98.43,2480.32 r0 top
FID2 "Fiducial" Fiducial10-20 640,300 r0 top
FID3 "Fiducial" Fiducial10-20 4320,300 r0 top
H1 "1902C" Keystone_1902C 205,2696.85 r180 bottom locked
H2 "NY PMS 440 0025 PH" "NY PMS 440 0025 PH" 205,2696.85 r0 top locked
H3 "1902C" Keystone_1902C 4750,3250 r180 bottom locked
H4 "NY PMS 440 0025 PH" "NY PMS 440 0025 PH" 4750,3250 r0 top locked
H5 "1902C" Keystone_1902C 200,200 r180 bottom locked
H6 "NY PMS 440 0025 PH" "NY PMS 440 0025 PH" 200,200 r0 top locked
H7 "1902C" Keystone_1902C 4750,200 r180 bottom locked
H8 "NY PMS 440 0025 PH" "NY PMS 440 0025 PH" 4750,200 r0 top locked
J1 "691253510002" FP-691253510002_CONN_TERM_BLOCK2-MFG 259.84,3151.18 r270 top
J10 "61300411121" WURTH_61300411121 4611.52,1685.85 r90 top
J30 "N2510-6002-RB" CONN_2510-6002 3720.31,557.5 r180 top
J100 "TSW-111-07-G-S" TSW-111-07-G-S#1 2622.99,1698.19 r0 top
J130 "KUSBX-MM-CS1-B30TR" FP-KUSBX-MM-CS1-B30TR_CONN_USB-MFG 4800,2145 r90 top locked
J200 "TSW-111-07-G-S" TSW-111-07-G-S#2 2623,498 r0 top locked
J230 "KUSBX-MM-CS1-B30TR" FP-KUSBX-MM-CS1-B30TR_CONN_USB-MFG 4800,945 r90 top locked
L1 "CM7060P701R-10" FP-CM7060P701R-10_SMT_CMC_7MM0_6MM0-MFG 1088.58,3135.26 r0 top
L2 "74438356010" WE-MAPI_4020 2362.2,3287.4 r90 top value=1uH
L100 "DNP" FP-XGL6060-103MEC_SMT_INDUCTOR-MFG 2198,2163 r0 top locked value=10uH
L101 "VCHA075D-8R2MS6" FP-VCHA075D-8R2MS6_SMD-MFG 2198,2163 r0 top locked
L200 "DNP" FP-XGL6060-103MEC_SMT_INDUCTOR-MFG 2198,963 r0 top locked value=10uH
L201 "VCHA075D-8R2MS6" FP-VCHA075D-8R2MS6_SMD-MFG 2198,963 r0 top locked
LBL1 "THT-14-423-10" Label_650x200 418.98,1410 r0 top
Logo1 "Texas Instruments" TI_Stacked_Overlay_Small 489.97,1820 r0 top
Logo2 "CE Mark" CE_Mark_5mm 356.56,1105 r0 top
Logo3 "FCC disclaimer" FCC_disclaimer 3509.25,2849.11 r0 top
Logo4 "WEEE logo" WEEE_Minimum 321.67,805 r0 top
Logo5 "CAUTION HOT SURFACE" IEC_HotSurface_Small 2243.37,2555 r0 top
Logo6 "CAUTION HOT SURFACE" IEC_HotSurface_Small 2247.46,1370 r0 top
NT100 "Net-Tie" Net-Tie_10mil 1935.4,2007.8 r0 top net-tie
NT200 "Net-Tie" Net-Tie_10mil 1935.66,808.02 r0 top net-tie
Q1 "NVMFS6H852NLT1G" FP-NVMFS6H852NLT1G_DFN5-MFG 1534.79,3181.97 r270 top
Q10 "PBSS4160T" SOT-23 3732.41,1949.74 r90 top value="60 V"
R1 "RCWE1020R118FKEA" FP-RCWE1020R118FKEA_1020-MFG 2372.05,2922.07 r90 top
R10 "CRCW06030000Z0EA" 0603 4072.28,2032.4 r180 top value=0
R11 "CRCW0603100KFKEA" 0603 4073.8,1965.63 r180 top value=100k
R12 "CRCW0603100KFKEA" 0603 4368.59,1440 r90 top value=100k
R13 "0" 0603 4438.86,1439.3 r270 top
R14 "CRCW06030000Z0EA" 0603 4008.31,1270.02 r180 top value=0
R15 "CRCW0603100KFKEA" 0603 4009.69,1345.52 r180 top value=100k
R16 "CRCW060310K0FKEA" 0603 4169.29,1434.5 r270 top value=10.0k
R19 "CRCW0603681KFKEA" 0603 4356.44,1820.25 r270 top value=681k
R20 "DNP" 0603 4438.86,1874.01 r90 top value=0
R21 "CRCW060310K0FKEA" 0603 4230.77,1424.91 r270 top value=10.0k
R22 "CRCW0603100KFKEA" 0603 4300.73,1428.5 r270 top value=100k
R23 "DNP" 0603 3821.17,2019.24 r180 top value=0
R24 "CRCW06030000Z0EA" 0603 3848.57,1922.03 r90 top value=0
R25 "CRCW0603100KFKEA" 0603 3625.85,1953.53 r270 top value=100k
R26 "CRCW0603100KFKEA" 0603 3741.41,1816.64 r0 top value=100k
R27 "ERJ3EKF2001V" 0603 4749.66,1592.16 r270 top value=2.00k
R28 "ERJ3EKF2001V" 0603 4752.43,1757.77 r90 top value=2.00k
R30 "ERJ3EKF2001V" 0603 3740,848.23 r0 top value=2.00k
R31 "ERJ3EKF2001V" 0603 3529.86,850.51 r0 top value=2.00k
R32 "DNP" 0603 3740,774.92 r0 top value=0
R100 "CRCW06033K48FKEA" 0603 1600.07,1854.74 r0 top value=3.48k
R101 "CRCW060320K0FKEA" 0603 2003.27,1805.73 r90 top value=20.0k
R102 "CRCW0603100KFKEA" 0603 1600.07,1918.65 r180 top value=100k
R104 "CRCW060341K2FKEA" 0603 1873.73,1710.58 r90 top value=41.2k
R105 "TMP6131QDYARQ1" DYA0002A-MFG 1910,2086 r180 bottom value=10kΩ
R106 "RC0603JR-070RL" 0603 1600.07,1984.35 r0 top value=0
R107 "CRCW060351R0JNEA" 0603 1735.67,1781.94 r270 top value=51
R108 "RC0603JR-070RL" 0603 1800.13,1781.94 r270 top value=0
R109 "placeholder" 0603 1928.64,2286.31 r270 top value=2.00
R110 "DNP" 0603 2392.52,1897.69 r270 top value=0
R111 "KRL2012M-R008-F-T1" KRL2012 2435,2023 r0 top locked value=0.008
R112 "RC0603JR-070RL" 0603 2457.43,1898.13 r90 top value=0
R113 "CRCW06035M10JNEA" 0603 1939.35,1676.58 r90 top value=5.1Meg
R135 "RC0603JR-070RL" 0603 4302,2212.29 r0 bottom value=0
R136 "RC0603JR-070RL" 0603 4450.14,2265.57 r0 bottom value=0
R137 "RC0603JR-070RL" 0603 4330.75,2083.11 r0 bottom value=0
R138 "RC0603JR-070RL" 0603 4332.44,2015.87 r0 bottom value=0
R200 "CRCW06033K48FKEA" 0603 1598.98,657.47 r0 top value=3.48k
R201 "CRCW060320K0FKEA" 0603 2005.37,598.42 r90 top value=20.0k
R202 "CRCW0603100KFKEA" 0603 1597.75,722.4 r180 top value=100k
R204 "CRCW060354K9FKEA" 0603 1874.04,501.85 r90 top value=54.9k
R205 "TMP6131QDYARQ1" DYA0002A-MFG 1910,886 r180 bottom value=10kΩ
R206 "RC0603JR-070RL" 0603 1596.61,787.05 r0 top value=0
R207 "CRCW060351R0JNEA" 0603 1738.51,579.92 r270 top value=51
R208 "RC0603JR-070RL" 0603 1803.55,579.92 r270 top value=0
R209 "placeholder" 0603 1926.7,1085.28 r270 top value=2.00
R210 "DNP" 0603 2385,701.47 r270 top value=0
R211 "KRL2012M-R008-F-T1" KRL2012 2435,823 r0 top locked value=0.008
R212 "RC0603JR-070RL" 0603 2447.81,699.97 r90 top value=0
R213 "CRCW06035M10JNEA" 0603 1941,470.35 r90 top value=5.1Meg
R235 "RC0603JR-070RL" 0603 4363.94,1032.48 r0 bottom value=0
R236 "RC0603JR-070RL" 0603 4447.74,1102.28 r0 bottom value=0
R237 "RC0603JR-070RL" 0603 4329.94,882.71 r0 bottom value=0
R238 "RC0603JR-070RL" 0603 4336.32,819.17 r0 bottom value=0
TP1 "5000" Keystone5000 578.45,3343.62 r90 top
TP2 "5001" Keystone5001 557.47,3006.73 r90 top
TP3 "5000" Keystone5000 3012.14,3239.74 r90 top
TP4 "5001" Keystone5001 3021.65,2903.09 r90 top
TP10 "TP_SM_1MM" TP_SM_1MM#1 4446.35,1573.69 r90 top
TP11 "TP_SM_1MM" TP_SM_1MM#1 4386.96,1547.5 r90 top
TP12 "TP_SM_1MM" TP_SM_1MM#2 4466.12,1766.38 r90 top
TP100 "5000" Keystone5000 3013.65,2397.41 r90 top
TP101 "5001" Keystone5001 2984.5,1961.46 r90 top
TP200 "5000" Keystone5000 3013.35,1215.51 r90 top
TP201 "5001" Keystone5001 3013.35,748.51 r90 top
U1 "LM74500QDDFQ1" DDF0008A-MFG 1370,2997.2 r0 top
U10 "TPS26744EAATRHBRQ1" RHB0032AA-MFG 4200,1640 r0 top
U100 "LM72650-Q1" RRX0029B-MFG 1857,2077 r0 top locked
U140 "TPD4S481QRGRRQ1" RGR0020C-MFG 4380,2160 r180 top
U200 "LM72650-Q1" RRX0029B-MFG 1857,877 r0 top locked
U240 "TPD4S481QRGRRQ1" RGR0020C-MFG 4380,960 r180 top
ZZ1 "This Assembly Note is for PCB labels only" AssemblyNoteLabel 185,3938 r0 top
ZZ2 "These assemblies are ESD sensitive, ESD precautions shall be observed." AssemblyNote 185,3829.11 r0 top
ZZ3 "These assemblies must be clean and free from flux and all contaminants. Use of no clean flux is not acceptable." AssemblyNote 185,3740.56 r0 top
ZZ4 "These assemblies must comply with workmanship standards IPC-A-610 Class 2, unless otherwise specified." AssemblyNote 185,3652 r0 top

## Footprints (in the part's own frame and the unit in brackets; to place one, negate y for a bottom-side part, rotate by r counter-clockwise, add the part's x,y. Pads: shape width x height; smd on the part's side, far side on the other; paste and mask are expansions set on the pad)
0603 [mm] "0603 from SM-752 data"
  rect 1x0.95 smd: 1(-0.8,0) 2(0.8,0)
  silkscreen extent -1.52,-0.69 1.52,0.69, body extent -0.87,-0.47 0.87,0.47, height 1
0603L [mm] "0603 from SM-752 data"
  rect 0.8x0.85 smd: 1(-0.7,0) 2(0.7,0)
  silkscreen extent -0.07,-0.33 0.07,0.33, body extent -0.87,-0.47 0.87,0.47, height 1
0805_HV [mil] "0805 with 30mil clearance between pads"
  rect 50x63 smd: 1(-40,0) 2(40,0)
  silkscreen extent -74,-40 74,40, body extent -43,-29 43,29, height 57
1206 [mm] "1206 from SM-752 data"
  rect 1.3x1.85 smd: 1(-1.45,0) 2(1.45,0)
  silkscreen extent -2.4,-1.21 2.4,1.21, body extent -1.7,-0.9 1.7,0.9, height 1.35
1206_180L [mm] "1206_180"
  rect 1.1x1.75 smd: 1(-1.35,0) 2(1.35,0)
  silkscreen extent -0.4,-0.77 0.4,0.77, body extent -1.75,-0.95 1.75,0.95, height 1.8
1210_220 [mm] "1210"
  rect 1.3x2.7 smd: 1(-1.45,0) 2(1.45,0)
  silkscreen extent -2.32,-1.57 2.32,1.57, body extent -1.7,-1.35 1.7,1.35, height 2.2
1210_220L [mm] "1210"
  rect 1.1x2.6 smd: 1(-1.35,0) 2(1.35,0)
  silkscreen extent -0.4,-1.2 0.4,1.2, body extent -1.7,-1.35 1.7,1.35, height 2.2
AssemblyNote [mil] "Assembly Note"
AssemblyNoteLabel [mil] "Assembly Note for PCB Labels"
CE_Mark_5mm [mil] "Minimum text height for CE Mark"
  silkscreen extent -138,-98 138,98
CONN_2510-6002 [mm] "3M 2500 series TS-0770-L December 15, 2011"
  rect 1.65x1.65 hole 1.016 mask+0: 1(-5.08,-1.27)
  round 1.65 hole 1.016 mask+0: 2(-5.08,1.27) 3(-2.54,-1.27) 4(-2.54,1.27) 5(0,-1.27) 6(0,1.27) 7(2.54,-1.27) 8(2.54,1.27) 9(5.08,-1.27) 10(5.08,1.27)
  silkscreen extent -10.01,-4.17 10.01,4.47, body extent -10.01,-4.11 10.01,4.52, height 9.92
DDF0008A-MFG [mm]
  rrect22% 1.05x0.45 smd paste+0 mask+0: 1(-1.3,0.975) 2(-1.3,0.325) 3(-1.3,-0.325) 4(-1.3,-0.975) 5(1.3,-0.975) 6(1.3,-0.325) 7(1.3,0.325) 8(1.3,0.975)
  silkscreen extent -2.5,-1.48 0.4,1.48, body extent -1.92,-1.73 1.92,1.73, height 0.25
DYA0002A-MFG [mm]
  rrect25% 0.67x0.4 smd paste+0 mask+0: 1(-0.74,0) 2(0.74,0)
  silkscreen extent -1.75,-0.63 0.65,0.63, body extent -0.8,-0.39 0.8,0.39, height 0.77
FCC_disclaimer [mil]
Fiducial10-20 [mm]
  round 1 smd mask+0.5: 1(0,0)
  Top Layer keep-out circle w1.178: c0,0 r0.5
FP-691253510002_CONN_TERM_BLOCK2-MFG [mm]
  rrect4% 2.3x2.3 hole 1.5 paste-1000 mask+0: 1(-2.24,-0.1)
  round 2.3 hole 1.5 paste-1000 mask+0: 2(2.84,-0.1)
  silkscreen extent -5.58,-6.25 5.58,5.65, body extent -5.68,-5.75 5.68,5.75, height 0.25
FP-CM7060P701R-10_SMT_CMC_7MM0_6MM0-MFG [mm]
  rrect7% 2.2x1.5 smd paste+0 mask+0: 1(-2.35,1.5) 2(-2.35,-1.5) 3(2.35,-1.5) 4(2.35,1.5)
  silkscreen extent -4.57,-3.25 3.85,3.25, body extent -3.95,-3.35 3.95,3.35, height 0.25
FP-KUSBX-MM-CS1-B30TR_CONN_USB-MFG [mm] "Recommended Land Pattern"
  rrect100% 1x1.8 hole 1.5 slot 0.7 at 0 deg paste-2539.97 mask+0: 1(-4.32,3.225) 2(4.32,3.225)
  rrect100% 1.65x1 hole 0.7 slot 1.35 at 0 deg paste-2539.97 mask+0: 1(-3.995,2.825) 2(3.995,2.825)
  rrect100% 1.3x1.9 hole 1.3 slot 0.7 at 0 deg paste-2539.97 mask+0: 3(-5.875,-2.375) 4(5.875,-2.375)
  rrect33% 0.3x0.85 smd paste+0 mask+0: A1(-2.65,3.75) A12(2.9,3.75) B1(2.65,2.15) B12(-2.9,2.15)
  rrect40% 0.25x0.85 smd paste+0 mask+0: A2(-2.125,3.75) A3(-1.625,3.75) A4(-1.125,3.75) A5(-0.625,3.75) A6(-0.125,3.75) A7(0.375,3.75) A8(0.875,3.75) A9(1.375,3.75) A10(1.875,3.75) A11(2.375,3.75) B2(2.125,2.15) B3(1.625,2.15) B4(1.125,2.15) B5(0.625,2.15) B6(0.125,2.15) B7(-0.375,2.15) B8(-0.875,2.15) B9(-1.375,2.15) B10(-1.875,2.15) B11(-2.375,2.15)
  Keep-Out Layer board cut-out: 4.725,-3.825 -4.725,-3.825 -4.725,0.425 -4.942,0.475 -5.116,0.613 -5.212,0.814 -5.212,1.036 -5.116,1.237 -4.942,1.375 -4.725,1.425 -4.725,1.425 4.725,1.425 4.942,1.375 5.116,1.237 5.212,1.036 5.212,0.814 5.116,0.613 4.942,0.475 4.725,0.425 4.725,0.425
  silkscreen extent -4.84,4.5 4.84,5.37, body extent -6.62,-4.6 6.63,4.6, height 0.25
FP-NVMFS6H852NLT1G_DFN5-MFG [mm]
  rrect13% 0.75x1 smd paste+0 mask+0: 1(-1.905,-2.748) 2(-0.635,-2.748) 3(0.635,-2.748) 4(1.905,-2.748)
  round 3.631 smd paste+0 mask+0: 5-6(-0.191,0.735)
  Top Layer region: -2.28,-1.282 -2.28,-0.857 -2.775,-0.857 -2.775,0.048 -2.28,0.048 -2.28,3.247 -1.53,3.247 -1.53,2.772 1.53,2.772 1.53,3.247 2.28,3.247 2.28,0.048 2.775,0.048 2.775,-0.857 2.28,-0.857 2.28,-1.282
  silkscreen extent -2.73,-3.95 2.73,3.05, body extent -2.88,-3.35 2.88,3.35, height 0.25
FP-RCWE1020R118FKEA_1020-MFG [mm]
  rrect8% 1.2x5.5 smd paste+0 mask+0: 1(-1.3,0) 2(1.3,0)
  silkscreen extent -0.32,-2.6 0.32,2.6, body extent -2,-2.85 2,2.85, height 0.25
FP-VCHA075D-8R2MS6_SMD-MFG [mm]
  rrect3% 3x3.5 smd paste+0 mask+0: 1(-2.8,0) 2(2.8,0)
  silkscreen extent -4.03,-3.75 4.03,3.75, body extent -4.4,-3.85 4.4,3.85, height 0.25
FP-XGL6060-103MEC_SMT_INDUCTOR-MFG [mm]
  rrect7% 1.43x5.5 smd paste+0 mask+0: 1(-2.02,0) 2(2.02,0)
  silkscreen extent -4.82,-3.45 3.35,3.45, body extent -3.45,-3.55 3.45,3.55, height 0.25
HXB_HA0 [mm] "SMD, 2-Leads, Dia 8mm"
  rrect3% 4.2x3.5 smd: 1(-3.2,0) 2(4.1,0)
  silkscreen extent -3.84,-4.23 4.6,4.28, body extent -4.22,-4.2 4.98,4.3, height 10.5
IEC_HotSurface_Small [mil]
  silkscreen extent -107,-93 107,92
Keystone5000 [mil] "For Keystone 500x miniature loop terminals"
  round 80 hole 40: 1(0,0)
  silkscreen extent -52,-52 52,52, body extent -49,-49 49,49, height 182
Keystone5001 [mil] "For Keystone 500x miniature loop terminals"
  round 80 hole 40: 1(0,0)
  silkscreen extent -52,-52 52,52, body extent -49,-49 49,49, height 182
Keystone_1902C [mil] "Hex Standoff, 4-40 threaded, nylon"
  round 1 on Mech4: 0(0,0)
  body extent -145,-126 146,126, height 501
KRL2012 [mm] "SUSUMU"
  rect 0.8x2.2 smd: 1(-0.7,0) 2(0.7,0)
  silkscreen extent -0.2,-1.35 0.2,1.35, body extent -0.72,-1.1 0.72,1.1, height 0.7
Label_650x200 [mil] "Thermal Transfer Label"
  round 1 on Mech13: 0(0,0)
  silkscreen extent -325,-100 325,100, body extent -325,-100 325,100, height 1
Net-Tie_10mil [mil] "10mil net tie, no solder mask opening, no solder paste"
  rect 10x10 smd paste-5 mask-5: 1(-10,0) 2(10,0)
  Top Layer region: -6,5 6,5 6,-5 -6,-5
"NY PMS 440 0025 PH" [mm] "4-40 nylon screw and mounting hole"
  round 8 hole 3.2: 1(0,0)
  body extent -3.3,-3.3 3.3,3.3, height 2.69
RGR0020C-MFG [mm]
  rrect42% 0.6x0.24 smd paste+0 mask+0: 1(-1.65,1) 2(-1.65,0.5) 3(-1.65,0) 4(-1.65,-0.5) 5(-1.65,-1) 11(1.65,-1) 12(1.65,-0.5) 13(1.65,0) 14(1.65,0.5) 15(1.65,1)
  rrect42% 0.24x0.6 smd paste+0 mask+0: 6(-1,-1.65) 7(-0.5,-1.65) 8(0,-1.65) 9(0.5,-1.65) 10(1,-1.65) 16(1,1.65) 17(0.5,1.65) 18(0,1.65) 19(-0.5,1.65) 20(-1,1.65)
  rrect5% 2.05x2.05 smd paste-1000 mask+0: 21(0,0)
  silkscreen extent -2.63,-1.83 1.83,1.83, body extent -2.05,-2.05 2.05,2.05, height 0.25
RHB0032AA-MFG [mm]
  rrect40% 0.6x0.25 smd paste+0 mask+0: 1(-2.4,1.75) 2(-2.4,1.25) 3(-2.4,0.75) 4(-2.4,0.25) 5(-2.4,-0.25) 6(-2.4,-0.75) 7(-2.4,-1.25) 8(-2.4,-1.75) 17(2.4,-1.75) 18(2.4,-1.25) 19(2.4,-0.75) 20(2.4,-0.25) 21(2.4,0.25) 22(2.4,0.75) 23(2.4,1.25) 24(2.4,1.75)
  rrect40% 0.25x0.6 smd paste+0 mask+0: 9(-1.75,-2.4) 10(-1.25,-2.4) 11(-0.75,-2.4) 12(-0.25,-2.4) 13(0.25,-2.4) 14(0.75,-2.4) 15(1.25,-2.4) 16(1.75,-2.4) 25(1.75,2.4) 26(1.25,2.4) 27(0.75,2.4) 28(0.25,2.4) 29(-0.25,2.4) 30(-0.75,2.4) 31(-1.25,2.4) 32(-1.75,2.4)
  rrect3% 3.7x3.7 smd paste-1000 mask+0: 33(0,0)
  silkscreen extent -3.37,-2.88 2.88,2.88, body extent -2.8,-2.8 2.8,2.8, height 0.25
RRX0029B-MFG [mm]
  rrect40% 0.267x0.25 smd paste+0 mask-1000: 1(-3.066,2.25) 2(-3.066,1.75)
  rrect40% 0.6x0.25 smd paste+0 mask+0: 3(-2.9,1.25) 4(-2.9,0.25) 5(-2.9,-0.25) 6(-2.9,-1.25) 7(-2.9,-1.75) 8(-2.9,-2.25) 17(2.9,-1.75) 18(2.9,-1.25) 19(2.9,-0.75)
  rrect40% 0.25x0.6 smd paste+0 mask+0: 9(-2,-2.9) 10(-1.5,-2.9) 11(-1,-2.9) 12(0,-2.9) 13(0.5,-2.9) 14(1,-2.9) 15(1.5,-2.9) 16(2,-2.9) 23(2,2.9) 24(1.5,2.9) 25(1,2.9) 26(0.5,2.9)
  rrect40% 0.293x0.25 smd paste+0 mask-1000: 20(3.054,0.75) 21(3.054,1.25) 22(3.054,1.75)
  rrect40% 0.25x0.258 smd paste+0 mask-1000: 27(-1,3.071) 28(-1.5,3.071) 29(-2,3.071)
  rrect6% 3.125x1.584 smd paste-1000 mask+0: 30(0.037,-1.308)
  Top Layer region: -3.27,3.22 -3.263,3.245 -3.245,3.263 -3.22,3.27 -3.22,3.27 -0.605,3.27 -0.586,3.266 -0.57,3.255 -0.559,3.239 -0.555,3.22 -0.555,3.22 -0.555,0.534 -0.564,0.488 -0.59,0.449 -0.629,0.423 -0.675,0.414 -0.675,0.414 -2.034,0.414 -2.08,0.423 -2.119,0.449 -2.145,0.488 -2.154,0.534 -2.154,0.534 -2.154,0.641 -2.158,0.66 -2.169,0.676 -2.185,0.687 -2.204,0.691 -2.204,0.691 -2.3,0.691 -2.346,0.7 -2.385,0.726 -2.411,0.765 -2.42,0.811 -2.42,0.811 -2.42,1.505 -2.427,1.53 -2.445,1.548 -2.47,1.555 -2.47,1.555 -3.15,1.555 -3.196,1.564 -3.235,1.59 -3.261,1.629 -3.27,1.675 -3.27,1.675
  Top Layer region: -0.08,2.17 -0.124,2.161 -0.161,2.136 -0.186,2.099 -0.195,2.055 -0.195,2.055 -0.195,0.185 -0.186,0.141 -0.161,0.104 -0.124,0.079 -0.08,0.07 -0.08,0.07 3.154,0.07 3.199,0.079 3.236,0.104 3.261,0.141 3.27,0.185 3.27,0.185 3.27,2.055 3.261,2.099 3.236,2.136 3.199,2.161 3.154,2.17 3.154,2.17
  silkscreen extent -3.87,-3.05 3.05,3.05, body extent -3.37,-3.3 3.37,3.37, height 0.25
SMB-Bi [mil] "Molded Diode, 2-Leads, Body 5.4x3.6mm, IPC Medium Density, based on OnSemi component dimensions"
  rect 85x107.99 smd: 1(-87.01,0) 2(87.01,0)
  silkscreen extent -125,-79 125,79, body extent -104,-73 104,73, height 89
SOT-23 [mm] "SOT23, 3-Leads, Body 2.9x1.3mm, Pitch 0.95mm, Lead Span 2.5mm, IPC Medium Density"
  rrect50% 1x0.6 smd: 1(-1.2,0.95) 2(-1.2,-0.95) 3(1.2,0)
  silkscreen extent -1.62,-1.5 0.7,1.5, body extent -1.16,-1.45 1.21,1.45, height 1
TG_V_1000x1020 [mm] "SMD, 2-Leads, 10 mm Dia, Pin Spacing 8.7 mm"
  rrect5% 4.1x2 smd: 1(-4.35,0) 2(4.35,0)
  body extent -5.8,-5.15 5.8,5.15, height 10.5
TI_Stacked_Overlay_Small [mil]
  silkscreen extent -418,-98 418,98
TP_SM_1MM#1 [mm] "1mm Test Point, SMT"
  round 1 smd paste-0.5: 1(0,0)
TP_SM_1MM#2 [mm] "1mm Test Point, SMT"
  round 1 smd far side paste-0.5: 1(0,0)
TSW-111-07-G-S#1 [mm] "Samtec 100mil, 1x11, 230 mil above insulator"
  rrect6% 1.65x1.65 hole 1.016: 1(-12.7,0)
  round 1.65 hole 1.016: 2(-10.16,0) 3(-7.62,0) 4(-5.08,0) 5(-2.54,0) 6(0,-0.005) 7(2.54,0) 8(5.08,0) 9(7.62,0) 10(10.16,0) 11(12.7,0)
  silkscreen extent -13.97,-1.27 13.97,1.65, body extent -13.97,-1.27 13.97,1.27, height 8.38
TSW-111-07-G-S#2 [mm] "Samtec 100mil, 1x11, 230 mil above insulator"
  rrect6% 1.65x1.65 hole 1.016: 1(-12.7,0)
  round 1.65 hole 1.016: 2(-10.16,0) 3(-7.62,0) 4(-5.08,0) 5(-2.54,0) 6(0,0) 7(2.54,0) 8(5.08,0) 9(7.62,0) 10(10.16,0) 11(12.7,0)
  silkscreen extent -13.97,-1.27 13.97,1.65, body extent -13.97,-1.27 13.97,1.27, height 8.38
WE-MAPI_4020 [mm] "SMD, 2-Leads, Body 4.1x4.1mm"
  rect 0.98x3.7 smd: 1(-1.185,0) 2(1.185,0)
  silkscreen extent -2.15,-2.15 2.15,2.15, body extent -2.15,-2.15 2.15,2.15, height 2.1
WEEE_Minimum [mil] "WEEElie bin"
  silkscreen extent -95,-172 99,104
WURTH_61300411121 [mm] "Header, 2.54mm, 4x1, TH"
  rrect50% 1.65x1.65 hole 1.15: 1(-3.81,0)
  round 1.65 hole 1.15: 2(-1.27,0) 3(1.27,0) 4(3.81,0)
  body extent -5.08,-1.27 5.08,1.27, height 8.54

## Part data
C0 C3 C106 C119 C206 C219: library part CMP-0007081-4, "CAP, CERM, 1000 pF, 100 V, +/- 10%, X7R, AEC-Q200 Grade 1, 0603", Cap_Case=0603, Manufacturer=TDK, Supplier Part Number 1=445-5806-1-ND, TempCo=X7R, Tolerance_%=10%, Value1="1.97137 ohm", Value2=100V, ValueDisplayed=1000pF
C1 C6 C10 C11 C140 C141 C240 C241: library part CMP-0064935-4, "CAP, CERM, 0.1 uF, 100 V,+/- 10%, X7R, AEC-Q200 Grade 1, 0603", Cap_Case=0603, Manufacturer=MuRata, Supplier Part Number 1=490-13420-1-ND, TempCo=X7R, Tolerance_%=10%, Value1=Unknown, Value2=100V, ValueDisplayed=0.1uF
C2: library part CMP-0008790-2, "CAP, CERM, 2.2 uF, 100 V, +/- 10%, X7S, AEC-Q200 Grade 1, 1206", Cap_Case=1206_180, Manufacturer=TDK, Supplier Part Number 1=445-6994-1-ND, TempCo=X7S, Tolerance_%=10%, Value1="0.005718 ohm", Value2=100V, ValueDisplayed=2.2uF
C4 C130 C230: library part CMP-0007144-4, "CAP, CERM, 0.1 uF, 50 V, +/- 10%, X7R, 0603", Cap_Case=0603, Manufacturer=MuRata, Supplier Part Number 1=490-4779-1-ND, TempCo=X7R, Tolerance_%=10%, Value1="0.02 ohm", Value2=50V, ValueDisplayed=0.1uF
C5 C9: library part CMP-0086185-1, "CAP, AL, 33 µF, 100 V, +/- 20%, 1 ohm, AEC-Q200 Grade 1, SMD", Cap_Case=10x10.2mm, Manufacturer=Panasonic, Tolerance_%=20%, Value1="1 ohm", Value2=100V, ValueDisplayed=33µF
C7 C8 C107 C108 C109 C207 C208 C209: library part CMP-0082268-1, "CAP, CERM, 4.7 µF, 100 V,+/- 10%, X7S, AEC-Q200 Grade 1, 1210", Cap_Case=1210, Manufacturer=MuRata, Supplier Part Number 1=490-14484-1-ND, TempCo=X7S, Tolerance_%=10%, Value1="0.001 ohm", Value2=100V, ValueDisplayed=4.7µF
C12: library part CMP-0079153-1, "CAP, CERM, 10 µF, 10 V,+/- 10%, X7R, AEC-Q200 Grade 1, 0805", Cap_Case=0805, Manufacturer=MuRata, Supplier Part Number 1=490-12646-1-ND, TempCo=X7R, Tolerance_%=10%, Value2=10V, ValueDisplayed=10µF
C13 C14: library part CMP-0007082-4, "CAP, CERM, 0.01 uF, 100 V, +/- 10%, X7R, AEC-Q200 Grade 1, 0603", Cap_Case=0603, Manufacturer=TDK, Supplier Part Number 1=445-5812-1-ND, TempCo=X7R, Tolerance_%=10%, Value1="0.235428 ohm", Value2=100V, ValueDisplayed=0.01uF
C15 C16 C17 C18: library part CMP-0007474-4, "CAP, CERM, 220 pF, 100 V, +/- 10%, X7R, 0603", Cap_Case=0603, Manufacturer=MuRata, Supplier Part Number 1=490-1460-1-ND, TempCo=X7R, Tolerance_%=10%, Value1=Unknown, Value2=100V, ValueDisplayed=220pF
C19 C103 C203: library part CMP-0007498-4, "CAP, CERM, 4.7 uF, 10 V, +/- 20%, X7R, 0603", Cap_Case=0603, Manufacturer=MuRata, TempCo=X7R, Tolerance_%=20%, Value1=Unknown, Value2=10V, ValueDisplayed=4.7uF
C20: library part CMP-0007142-4, "CAP, CERM, 0.47 uF, 25 V, +/- 10%, X7R, AEC-Q200 Grade 1, 0603", Cap_Case=0603, Manufacturer=MuRata, Supplier Part Number 1=490-4776-1-ND, TempCo=X7R, Tolerance_%=10%, Value1=Unknown, Value2=25V, ValueDisplayed=0.47uF
C21: library part CMP-0081259-1, "CAP, CERM, 1 µF, 35 V,+/- 10%, X7R, AEC-Q200 Grade 1, 0603", Cap_Case=0603, Manufacturer=TDK, Supplier Part Number 1=445-174339-1-ND, TempCo=X7R, Tolerance_%=10%, Value2=35V, ValueDisplayed=1µF
C100 C200: library part CMP-0084283-1, "CAP, CERM, 10 pF, 100 V,+/- 5%, C0G/NP0, AEC-Q200 Grade 1, 0603", Cap_Case=0603, Manufacturer=MuRata, TempCo=C0G/NP0, Tolerance_%=5%, Value2=100V, ValueDisplayed=10pF
C101 C201: library part CMP-0007148-4, "CAP, CERM, 3300 pF, 100 V, +/- 10%, X7R, AEC-Q200 Grade 1, 0603", Cap_Case=0603, Manufacturer=MuRata, Supplier Part Number 1=GCM188R72A332KA37D-ND, TempCo=X7R, Tolerance_%=10%, Value1=Unknown, Value2=100V, ValueDisplayed=3300pF
C102 C202: library part CMP-0084283-1, "CAP, CERM, 10 pF, 100 V,+/- 5%, C0G/NP0, AEC-Q200 Grade 1, 0603", Cap_Case=0603, Manufacturer=MuRata, TempCo=C0G/NP0, Tolerance_%=5%, Value2=100V, ValueDisplayed=placeholder
C104 C204: library part CMP-0079996-1, "CAP, CERM, 22 µF, 6.3 V,+/- 20%, X6S, 0603", Cap_Case=0603, Manufacturer=MuRata, Supplier Part Number 1=490-10471-1-ND, TempCo=X6S, Tolerance_%=20%, Value2=6.3V, ValueDisplayed=22µF
C105 C118 C205 C218: library part CMP-0007101-4, "CAP, CERM, 0.047 uF, 100 V, +/- 10%, X7S, AEC-Q200 Grade 1, 0603", Cap_Case=0603, Manufacturer=TDK, Supplier Part Number 1=445-6936-1-ND, TempCo=X7S, Tolerance_%=10%, Value1="0.089796 ohm", Value2=100V, ValueDisplayed=0.047uF
C110 C210: library part CMP-0007079-4, "CAP, CERM, 0.047 uF, 50 V, +/- 10%, X7R, AEC-Q200 Grade 1, 0603", Cap_Case=0603, Manufacturer=TDK, Supplier Part Number 1=445-5664-1-ND, TempCo=X7R, Tolerance_%=10%, Value1="0.049007 ohm", Value2=50V, ValueDisplayed=0.047uF
C111 C211: library part CMP-0007076-4, "CAP, CERM, 33 pF, 50 V, +/- 5%, C0G/NP0, AEC-Q200 Grade 0, 0603", Cap_Case=0603, Manufacturer=TDK, Supplier Part Number 1=445-12409-1-ND, TempCo=C0G/NP0, Tolerance_%=5%, Value1=Unknown, Value2=50V, ValueDisplayed=33pF
C112 C212: library part CMP-0007237-4, "CAP, CERM, 100 pF, 100 V, +/- 5%, C0G/NP0, 0603", Cap_Case=0603, Manufacturer=MuRata, PartNumber=GRM1885C2A101JA01D, Supplier Part Number 1=490-1351-1-ND, TempCo=C0G/NP0, Tolerance_%=5%, Value1=Unknown, Value2=100V, ValueDisplayed=100pF
C113 C114 C115 C116 C213 C214 C215 C216: library part CMP-0009150-2, "CAP, CERM, 4.7 uF, 100 V, +/- 10%, X7S, AEC-Q200 Grade 1, 1210", Cap_Case=1210_220, Manufacturer=TDK, Supplier Part Number 1=445-7005-1-ND, TempCo=X7S, Tolerance_%=10%, Value1="0.004236 ohm", Value2=100V, ValueDisplayed=4.7uF
C117 C217: library part CMP-0012270-3, "CAP, Aluminum Polymer, 47 uF, 50 V, +/- 20%, 0.03 ohm, AEC-Q200 Grade 2, D8xL10mm SMD", Cap_Case=HA0, Manufacturer=Chemi-Con, PartNumber=HHXB500ARA470MHA0G, Tolerance_%=20%, Value1="0.03 ohm", Value2=50V, ValueDisplayed=47uF
C131 C231: library part CMP-0008818-2, "CAP, CERM, 1 uF, 50 V, +/- 10%, X7R, AEC-Q200 Grade 1, 1206", Cap_Case=1206, Manufacturer=MuRata, Supplier Part Number 1=490-4795-1-ND, TempCo=X7R, Tolerance_%=10%, Value1=Unknown, Value2=50V, ValueDisplayed=1uF
D1: library part CMP-0005587-3, "Diode, TVS, Bi, 70 V, SMB", Manufacturer="Diodes Inc.", Value1=600W
D130 D131 D230 D231: library part CMP-0005927-3, "Diode, TVS, Uni, 5 V, SOT-23", Manufacturer="ON Semiconductor", Value1=300W
FID1 FID2 FID3: library part CMP-0077181-1, "Fiducial mark.  There is nothing to buy or mount.", Manufacturer=N/A
H1 H3 H5 H7: library part CMP-0003610-1, "Standoff, Hex, 0.5\"L #4-40 Nylon", Manufacturer=Keystone, Supplier Part Number 1=36-1902C-ND
H2 H4 H6 H8: library part CMP-0003617-1, "Machine Screw, Round, #4-40 x 1/4, Nylon, Philips panhead", Manufacturer="B&F Fastener Supply", Supplier Part Number 1=H542-ND
J1: library part CMP-0095936-2, "2 Position Wire to Board Terminal Block Horizontal with Board 0.200\" (5.08mm) Through Hole", Current_A=16A, Digikey Part Number=732-691253510002-ND, Manufacturer="Wurth Electronics", Mouser Part Number=710-691253510002, Operating Temperature Range="-30°C to +120°C", Voltage_V=300V
J10: library part CMP-0054798-2, "Header, 2.54 mm, 4x1, Gold, TH", Color=Black, Manufacturer="Wurth Elektronik", Supplier Part Number 1=732-5317-ND
J30: library part CMP-0055448-2, "Header (shrouded), 100mil, 5x2, High-Temperature, Gold, TH", Manufacturer=3M, Supplier Part Number 1=MHC10K-ND
J100 J200: library part CMP-0075454-1, "Header, 100mil, 11x1, Gold, TH", Color=Black, Current_A=6.3A, Manufacturer=Samtec, Supplier Part Number 1=SAM1029-11-ND, Voltage_V=550V
J130 J230: library part CMP-0124069-1, "USB Connectors USB TYPE C SOCKET MIDMOUNT BLK 30u T/R", Digikey Part Number=2092-KUSBX-MM-CS1-B30CT-ND, Manufacturer=Kycon, Mouser Part Number=806-KUSBX-MMCS1B30TR, Operating Temperature Range="-55°C to +105°C", Voltage_V=30V
L1: library part CMP-0094039-1, "Common Mode Choke Power 700Ω 4A -40 to 125°C Wire Wound Surface Mount T/R", Digikey Part Number=240-2978-1-ND, Impedance At Frequency="700Ω @ 100MHz", Manufacturer=Laird, Mouser Part Number=739-CM7060P701R-10, Operating Temperature Range="-40°C to +125°C"
L2: library part CMP-0064168-1, "Inductor, Shielded, 1 uH, 7.2 A, 0.012 ohm, SMD", Manufacturer="Wurth Elektronik", Value1="0.012 ohm", Value2=7.2A, ValueDisplayed=1uH
L100 L200: library part CMP-0091525-1, "Power Inductor, shielded, composite, 20% tol, SMT, RoHS, halogen-free", Manufacturer=Coilcraft, Operating Temperature Range="to +165°C", Part Number=XGL6060-103MEC, Self Resonant Frequency=14MHz, Test Frequency=1MHz, Tolerance_%=20%
L101 L201: library part CMP-0089036-1, "Power Choke Coil", Manufacturer=Cyntec
LBL1: library part CMP-0003625-1, "Thermal Transfer Printable Labels, 0.650\" W x 0.200\" H - 10,000 per roll", Manufacturer=Brady, Supplier Part Number 1=97C5133
Logo1: library part CMP-0074838-1, "Texas Instrument Corporate Signature"
Logo2: library part CMP-0074844-1
Logo3: library part CMP-0074847-1, "FCC_disclaimer"
Logo4: library part CMP-0074769-1
Logo5 Logo6: library part CMP-0074837-2, "IEC 61010-1 Hot Surface Warning", Manufacturer="Texas Instruments"
NT100 NT200: library part CMP-0078142-6, "Single point connection between nets.", Manufacturer=N/A
Q1: library part CMP-0122137-1, "N-Channel 80 V 11A (Ta), 42A (Tc) 3.6W (Ta), 54W (Tc) Surface Mount 5-DFN (5x6) (8-SOFL)", Digikey Part Number=488-NVMFS6H852NLT1GCT-ND, Drain To Source Breakdown Voltage=80V, Input Capacitace At Vds="906pF @ 40V", Manufacturer=onsemi, Mouser Part Number=863-NVMFS6H852NLT1G, Operating Temperature Range="-55°C to +175°C", Power_W=3.6W, Pulse Drain Current=208A, Typ Forward Diode Voltage=0.81V
Q10: library part CMP-0000389-2, "Transistor, NPN, 60 V, 0.9 A, SOT-23", Manufacturer="NXP Semiconductor", Supplier Part Number 1=568-4343-1-ND, Value1="0.9 A"
R1: library part CMP-0087670-1, "118 mOhms ±1% 2W Chip Resistor Wide 2010 (5025 Metric), 1020 Automotive AEC-Q200, Current Sense, Moisture Resistant Thick Film", Manufacturer=Vishay, Power_W=2W, TempCo=100ppm/°C, Tolerance_%=1%
R10 R14 R24: library part CMP-0025697-4, "RES, 0, 5%, 0.1 W, AEC-Q200 Grade 0, 0603", Manufacturer=Vishay-Dale, Power_W=100mW, Supplier Part Number 1=541-0.0GCT-ND, TempCo="200 ppm/C", Tolerance_%=5%, Value2=0.1W, Value_Code=0000, ValueDisplayed=0
R11 R12 R15 R22 R25 R26 R102 R202: library part CMP-0021990-4, "RES, 100 k, 1%, 0.1 W, AEC-Q200 Grade 0, 0603", Manufacturer=Vishay-Dale, Power_W=100mW, Supplier Part Number 1=541-100KHCT-ND, TempCo="100 ppm/C", Tolerance_%=1%, Value2=0.1W, Value_Code=100k
R13: library part CMP-0025885-5, "RES, 0, 5%, 0.1 W, 0603", Manufacturer=Yageo, PartNumber=RC0603JR-070RL, Power_W=100mW, Supplier Part Number 1=311-0.0GRCT-ND, TempCo="200 ppm/C", Tolerance_%=5%, Value2=0.1W, Value_Code=0000
R16 R21: library part CMP-0021998-4, "RES, 10.0 k, 1%, 0.1 W, AEC-Q200 Grade 0, 0603", Manufacturer=Vishay-Dale, Power_W=100mW, Supplier Part Number 1=541-10.0KHCT-ND, TempCo="100 ppm/C", Tolerance_%=1%, Value2=0.1W, Value_Code=10k0, ValueDisplayed=10.0k
R19: library part CMP-0022550-4, "RES, 681 k, 1%, 0.1 W, AEC-Q200 Grade 0, 0603", Manufacturer=Vishay-Dale, Power_W=100mW, Supplier Part Number 1=541-681KHCT-ND, TempCo="100 ppm/C", Tolerance_%=1%, Value2=0.1W, Value_Code=681k
R20 R23 R32 R110 R210: library part CMP-0025885-5, "RES, 0, 5%, 0.1 W, 0603", Manufacturer=Yageo, PartNumber=RC0603JR-070RL, Power_W=100mW, Supplier Part Number 1=311-0.0GRCT-ND, TempCo="200 ppm/C", Tolerance_%=5%, Value2=0.1W, Value_Code=0000, ValueDisplayed=0
R27 R28 R30 R31: library part CMP-0078663-1, "RES, 2.00 k, 1%, 0.1 W, AEC-Q200 Grade 0, 0603", Manufacturer=Panasonic, Power_W=100mW, Supplier Part Number 1=P2.00KHCT-ND, TempCo="100 ppm/C", Tolerance_%=1%, Value2=0.1W, Value_Code=2k00, ValueDisplayed=2.00k
R100 R200: library part CMP-0022377-4, "RES, 3.48 k, 1%, 0.1 W, AEC-Q200 Grade 0, 0603", Manufacturer=Vishay-Dale, Power_W=100mW, Supplier Part Number 1=541-3.48KHCT-ND, TempCo="100 ppm/C", Tolerance_%=1%, Value2=0.1W, Value_Code=3k48, ValueDisplayed=3.48k
R101 R201: library part CMP-0022204-4, "RES, 20.0 k, 1%, 0.1 W, AEC-Q200 Grade 0, 0603", Manufacturer=Vishay-Dale, Power_W=100mW, Supplier Part Number 1=541-20.0KHCT-ND, TempCo="100 ppm/C", Tolerance_%=1%, Value2=0.1W, Value_Code=20k0, ValueDisplayed=20.0k
R104: library part CMP-0022414-4, "RES, 41.2 k, 1%, 0.1 W, AEC-Q200 Grade 0, 0603", Manufacturer=Vishay-Dale, Power_W=100mW, Supplier Part Number 1=541-41.2KHCT-ND, TempCo="100 ppm/C", Tolerance_%=1%, Value2=0.1W, Value_Code=41k2, ValueDisplayed=41.2k
R105 R205: library part CMP-0123120-1, "Automotive ±1% tolerance 10kΩ linear thermistor available in an 0402 package option 2-SOT-5X3 -40 to 150", Digikey Part Number=296-TMP6131QDYARQ1CT-ND, Manufacturer="Texas Instruments", Max Current=400uA, Mouser Part Number=595-TMP6131QDYARQ1, Operating Temperature Range="-40°C to +150°C", TempCo=6400ppm/°C, Tolerance_%=1%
